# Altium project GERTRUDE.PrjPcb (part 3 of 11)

## Sheet MODULE_SAIL.SchDoc: MODULE SAIL
size A3; Author: Silvio Navaretti; CompanyName: ARDUINO; DrawnBy: Silvio Navaretti; Engineer: Silvio Navaretti; Organization: ARDUINO; SheetNumber: 4; SheetTotal: 51; RevAuthor: Silvio Navaretti
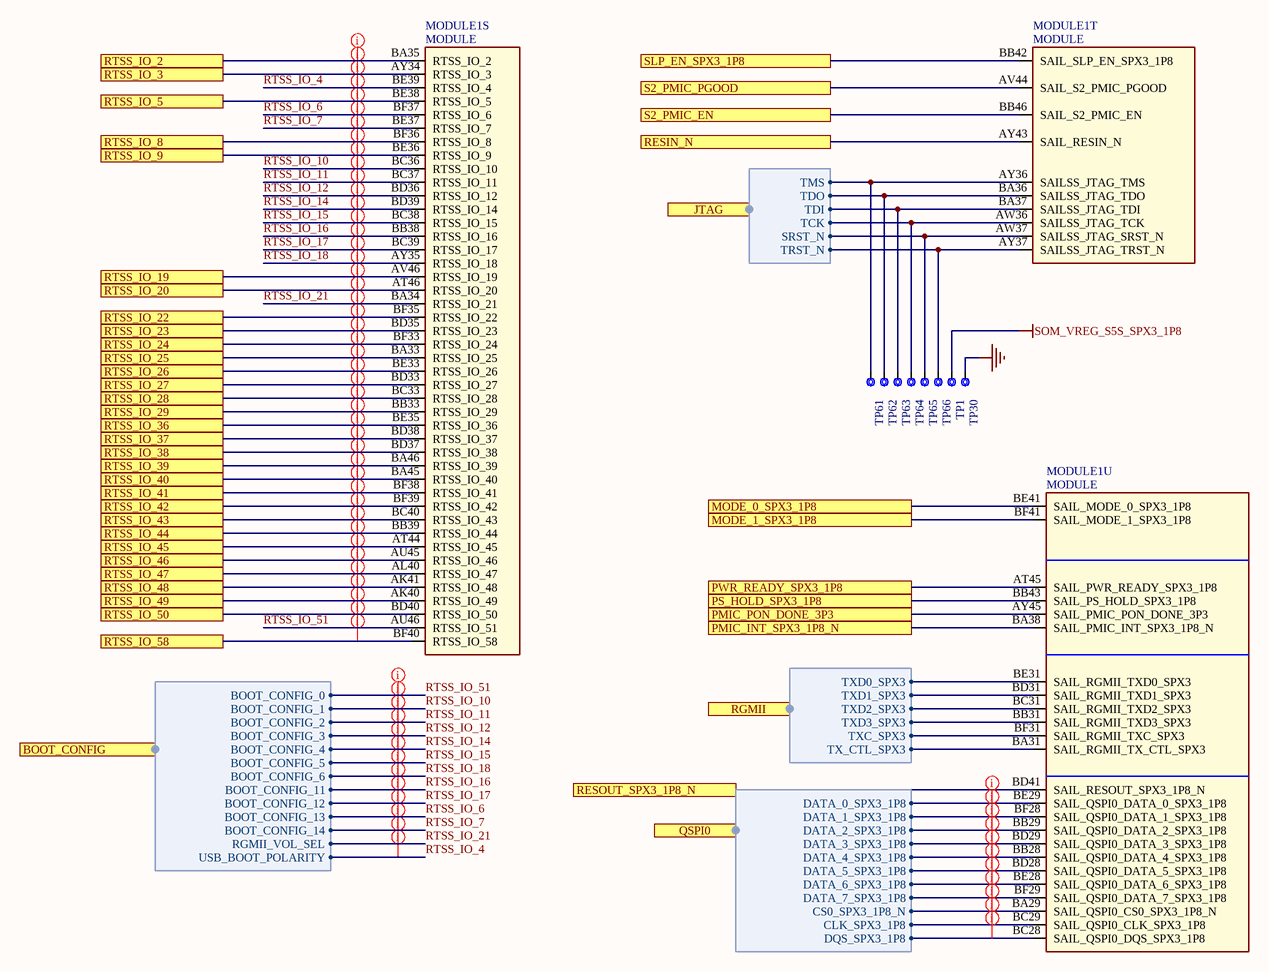
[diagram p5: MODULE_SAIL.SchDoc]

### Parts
MODULE1  MODULE  [MODULE]  (parts S,T,U of 22)
TP1  Test point 1.00mm  [TP-1.00MM]  (value not drawn)  (no BOM)
TP30  Test point 1.00mm  [TP-1.00MM]  (value not drawn)  (no BOM)
TP61  Test point 1.00mm  [TP-1.00MM]  (value not drawn)  (no BOM)
TP62  Test point 1.00mm  [TP-1.00MM]  (value not drawn)  (no BOM)
TP63  Test point 1.00mm  [TP-1.00MM]  (value not drawn)  (no BOM)
TP64  Test point 1.00mm  [TP-1.00MM]  (value not drawn)  (no BOM)
TP65  Test point 1.00mm  [TP-1.00MM]  (value not drawn)  (no BOM)
TP66  Test point 1.00mm  [TP-1.00MM]  (value not drawn)  (no BOM)

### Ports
BOOT_CONFIG (harness SOM_SAIL_BOOT_CONFIG), JTAG (harness SOM_SAIL_JTAG), MODE_0_SPX3_1P8, MODE_1_SPX3_1P8, PMIC_INT_SPX3_1P8_N, PMIC_PON_DONE_3P3, PS_HOLD_SPX3_1P8, PWR_READY_SPX3_1P8, QSPI0 (harness SOM_SAIL_QSPI0), RESIN_N, RESOUT_SPX3_1P8_N, RGMII (harness SOM_SAIL_RGMII), RTSS_IO_2, RTSS_IO_3, RTSS_IO_5, RTSS_IO_8, RTSS_IO_9, RTSS_IO_19, RTSS_IO_20, RTSS_IO_22, RTSS_IO_23, RTSS_IO_24, RTSS_IO_25, RTSS_IO_26, RTSS_IO_27, RTSS_IO_28, RTSS_IO_29, RTSS_IO_36, RTSS_IO_37, RTSS_IO_38, RTSS_IO_39, RTSS_IO_40, RTSS_IO_41, RTSS_IO_42, RTSS_IO_43, RTSS_IO_44, RTSS_IO_45, RTSS_IO_46, RTSS_IO_47, RTSS_IO_48, RTSS_IO_49, RTSS_IO_50, RTSS_IO_58, S2_PMIC_EN, S2_PMIC_PGOOD, SLP_EN_SPX3_1P8

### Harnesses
SOM_SAIL_JTAG: TMS, TDO, TDI, TCK, SRST_N, TRST_N
SOM_SAIL_RGMII: TXD0_SPX3, TXD1_SPX3, TXD2_SPX3, TXD3_SPX3, TXC_SPX3, TX_CTL_SPX3
SOM_SAIL_QSPI0: DATA_0_SPX3_1P8, DATA_1_SPX3_1P8, DATA_2_SPX3_1P8, DATA_3_SPX3_1P8, DATA_4_SPX3_1P8, DATA_5_SPX3_1P8, DATA_6_SPX3_1P8, DATA_7_SPX3_1P8, CS0_SPX3_1P8_N, CLK_SPX3_1P8, DQS_SPX3_1P8
SOM_SAIL_BOOT_CONFIG: BOOT_CONFIG_0, BOOT_CONFIG_1, BOOT_CONFIG_2, BOOT_CONFIG_3, BOOT_CONFIG_4, BOOT_CONFIG_5, BOOT_CONFIG_6, BOOT_CONFIG_11, BOOT_CONFIG_12, BOOT_CONFIG_13, BOOT_CONFIG_14, RGMII_VOL_SEL, USB_BOOT_POLARITY

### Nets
GND: TP30.X
SOM_VREG_S5S_SPX3_1P8: TP1.X
RTSS_IO_4: MODULE1.BE39(RTSS_IO_4) ; port BOOT_CONFIG.USB_BOOT_POLARITY
RTSS_IO_6: MODULE1.BF37(RTSS_IO_6) ; port BOOT_CONFIG.BOOT_CONFIG_13
RTSS_IO_7: MODULE1.BE37(RTSS_IO_7) ; port BOOT_CONFIG.BOOT_CONFIG_14
RTSS_IO_10: MODULE1.BC36(RTSS_IO_10) ; port BOOT_CONFIG.BOOT_CONFIG_1
RTSS_IO_11: MODULE1.BC37(RTSS_IO_11) ; port BOOT_CONFIG.BOOT_CONFIG_2
RTSS_IO_12: MODULE1.BD36(RTSS_IO_12) ; port BOOT_CONFIG.BOOT_CONFIG_3
RTSS_IO_14: MODULE1.BD39(RTSS_IO_14) ; port BOOT_CONFIG.BOOT_CONFIG_4
RTSS_IO_15: MODULE1.BC38(RTSS_IO_15) ; port BOOT_CONFIG.BOOT_CONFIG_5
RTSS_IO_16: MODULE1.BB38(RTSS_IO_16) ; port BOOT_CONFIG.BOOT_CONFIG_11
RTSS_IO_17: MODULE1.BC39(RTSS_IO_17) ; port BOOT_CONFIG.BOOT_CONFIG_12
RTSS_IO_18: MODULE1.AY35(RTSS_IO_18) ; port BOOT_CONFIG.BOOT_CONFIG_6
RTSS_IO_21: MODULE1.BA34(RTSS_IO_21) ; port BOOT_CONFIG.RGMII_VOL_SEL
RTSS_IO_51: MODULE1.AU46(RTSS_IO_51) ; port BOOT_CONFIG.BOOT_CONFIG_0
RTSS_IO_58_FORCE_USB_BOOT_SPX3_1P8: MODULE1.BF40(RTSS_IO_58) ; port RTSS_IO_58
RTSS_RESIN_N: MODULE1.AY43(SAIL_RESIN_N) ; port RESIN_N
SAIL_JTAG.SRST_N: MODULE1.AW37(SAILSS_JTAG_SRST_N) TP65.X ; port JTAG.SRST_N
SAIL_JTAG.TCK: MODULE1.AW36(SAILSS_JTAG_TCK) TP64.X ; port JTAG.TCK
SAIL_JTAG.TDI: MODULE1.BA37(SAILSS_JTAG_TDI) TP63.X ; port JTAG.TDI
SAIL_JTAG.TDO: MODULE1.BA36(SAILSS_JTAG_TDO) TP62.X ; port JTAG.TDO
SAIL_JTAG.TMS: MODULE1.AY36(SAILSS_JTAG_TMS) TP61.X ; port JTAG.TMS
SAIL_JTAG.TRST_N: MODULE1.AY37(SAILSS_JTAG_TRST_N) TP66.X ; port JTAG.TRST_N
NetMODULE1_AK40: MODULE1.AK40(RTSS_IO_49) ; port RTSS_IO_49
NetMODULE1_AK41: MODULE1.AK41(RTSS_IO_48) ; port RTSS_IO_48
NetMODULE1_AL40: MODULE1.AL40(RTSS_IO_47) ; port RTSS_IO_47
NetMODULE1_AT44: MODULE1.AT44(RTSS_IO_45) ; port RTSS_IO_45
NetMODULE1_AT45: MODULE1.AT45(SAIL_PWR_READY_SPX3_1P8) ; port PWR_READY_SPX3_1P8
NetMODULE1_AT46: MODULE1.AT46(RTSS_IO_20) ; port RTSS_IO_20
NetMODULE1_AU45: MODULE1.AU45(RTSS_IO_46) ; port RTSS_IO_46
NetMODULE1_AV44: MODULE1.AV44(SAIL_S2_PMIC_PGOOD) ; port S2_PMIC_PGOOD
NetMODULE1_AV46: MODULE1.AV46(RTSS_IO_19) ; port RTSS_IO_19
NetMODULE1_AY34: MODULE1.AY34(RTSS_IO_3) ; port RTSS_IO_3
NetMODULE1_AY45: MODULE1.AY45(SAIL_PMIC_PON_DONE_3P3) ; port PMIC_PON_DONE_3P3
NetMODULE1_BA29: MODULE1.BA29(SAIL_QSPI0_CS0_SPX3_1P8_N) ; port QSPI0.CS0_SPX3_1P8_N
NetMODULE1_BA31: MODULE1.BA31(SAIL_RGMII_TX_CTL_SPX3) ; port RGMII.TX_CTL_SPX3
NetMODULE1_BA33: MODULE1.BA33(RTSS_IO_25) ; port RTSS_IO_25
NetMODULE1_BA35: MODULE1.BA35(RTSS_IO_2) ; port RTSS_IO_2
NetMODULE1_BA38: MODULE1.BA38(SAIL_PMIC_INT_SPX3_1P8_N) ; port PMIC_INT_SPX3_1P8_N
NetMODULE1_BA45: MODULE1.BA45(RTSS_IO_40) ; port RTSS_IO_40
NetMODULE1_BA46: MODULE1.BA46(RTSS_IO_39) ; port RTSS_IO_39
NetMODULE1_BB28: MODULE1.BB28(SAIL_QSPI0_DATA_4_SPX3_1P8) ; port QSPI0.DATA_4_SPX3_1P8
NetMODULE1_BB29: MODULE1.BB29(SAIL_QSPI0_DATA_2_SPX3_1P8) ; port QSPI0.DATA_2_SPX3_1P8
NetMODULE1_BB31: MODULE1.BB31(SAIL_RGMII_TXD3_SPX3) ; port RGMII.TXD3_SPX3
NetMODULE1_BB33: MODULE1.BB33(RTSS_IO_29) ; port RTSS_IO_29
NetMODULE1_BB39: MODULE1.BB39(RTSS_IO_44) ; port RTSS_IO_44
NetMODULE1_BB42: MODULE1.BB42(SAIL_SLP_EN_SPX3_1P8) ; port SLP_EN_SPX3_1P8
NetMODULE1_BB43: MODULE1.BB43(SAIL_PS_HOLD_SPX3_1P8) ; port PS_HOLD_SPX3_1P8
NetMODULE1_BB46: MODULE1.BB46(SAIL_S2_PMIC_EN) ; port S2_PMIC_EN
NetMODULE1_BC28: MODULE1.BC28(SAIL_QSPI0_DQS_SPX3_1P8) ; port QSPI0.DQS_SPX3_1P8
NetMODULE1_BC29: MODULE1.BC29(SAIL_QSPI0_CLK_SPX3_1P8) ; port QSPI0.CLK_SPX3_1P8
NetMODULE1_BC31: MODULE1.BC31(SAIL_RGMII_TXD2_SPX3) ; port RGMII.TXD2_SPX3
NetMODULE1_BC33: MODULE1.BC33(RTSS_IO_28) ; port RTSS_IO_28
NetMODULE1_BC40: MODULE1.BC40(RTSS_IO_43) ; port RTSS_IO_43
NetMODULE1_BD28: MODULE1.BD28(SAIL_QSPI0_DATA_5_SPX3_1P8) ; port QSPI0.DATA_5_SPX3_1P8
NetMODULE1_BD29: MODULE1.BD29(SAIL_QSPI0_DATA_3_SPX3_1P8) ; port QSPI0.DATA_3_SPX3_1P8
NetMODULE1_BD31: MODULE1.BD31(SAIL_RGMII_TXD1_SPX3) ; port RGMII.TXD1_SPX3
NetMODULE1_BD33: MODULE1.BD33(RTSS_IO_27) ; port RTSS_IO_27
NetMODULE1_BD35: MODULE1.BD35(RTSS_IO_23) ; port RTSS_IO_23
NetMODULE1_BD37: MODULE1.BD37(RTSS_IO_38) ; port RTSS_IO_38
NetMODULE1_BD38: MODULE1.BD38(RTSS_IO_37) ; port RTSS_IO_37
NetMODULE1_BD40: MODULE1.BD40(RTSS_IO_50) ; port RTSS_IO_50
NetMODULE1_BD41: MODULE1.BD41(SAIL_RESOUT_SPX3_1P8_N) ; port RESOUT_SPX3_1P8_N
NetMODULE1_BE28: MODULE1.BE28(SAIL_QSPI0_DATA_6_SPX3_1P8) ; port QSPI0.DATA_6_SPX3_1P8
NetMODULE1_BE29: MODULE1.BE29(SAIL_QSPI0_DATA_0_SPX3_1P8) ; port QSPI0.DATA_0_SPX3_1P8
NetMODULE1_BE31: MODULE1.BE31(SAIL_RGMII_TXD0_SPX3) ; port RGMII.TXD0_SPX3
NetMODULE1_BE33: MODULE1.BE33(RTSS_IO_26) ; port RTSS_IO_26
NetMODULE1_BE35: MODULE1.BE35(RTSS_IO_36) ; port RTSS_IO_36
NetMODULE1_BE36: MODULE1.BE36(RTSS_IO_9) ; port RTSS_IO_9
NetMODULE1_BE38: MODULE1.BE38(RTSS_IO_5) ; port RTSS_IO_5
NetMODULE1_BE41: MODULE1.BE41(SAIL_MODE_0_SPX3_1P8) ; port MODE_0_SPX3_1P8
NetMODULE1_BF28: MODULE1.BF28(SAIL_QSPI0_DATA_1_SPX3_1P8) ; port QSPI0.DATA_1_SPX3_1P8
NetMODULE1_BF29: MODULE1.BF29(SAIL_QSPI0_DATA_7_SPX3_1P8) ; port QSPI0.DATA_7_SPX3_1P8
NetMODULE1_BF31: MODULE1.BF31(SAIL_RGMII_TXC_SPX3) ; port RGMII.TXC_SPX3
NetMODULE1_BF33: MODULE1.BF33(RTSS_IO_24) ; port RTSS_IO_24
NetMODULE1_BF35: MODULE1.BF35(RTSS_IO_22) ; port RTSS_IO_22
NetMODULE1_BF36: MODULE1.BF36(RTSS_IO_8) ; port RTSS_IO_8
NetMODULE1_BF38: MODULE1.BF38(RTSS_IO_41) ; port RTSS_IO_41
NetMODULE1_BF39: MODULE1.BF39(RTSS_IO_42) ; port RTSS_IO_42
NetMODULE1_BF41: MODULE1.BF41(SAIL_MODE_1_SPX3_1P8) ; port MODE_1_SPX3_1P8

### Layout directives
net class NET_SOM_SAIL_BOOT: RTSS_IO_4, RTSS_IO_6, RTSS_IO_7, RTSS_IO_10, RTSS_IO_11, RTSS_IO_12, RTSS_IO_14, RTSS_IO_15, RTSS_IO_16, RTSS_IO_17, RTSS_IO_18, RTSS_IO_21, RTSS_IO_51
net class NET_SOM_SAIL_IO: NetMODULE1_AK40, NetMODULE1_AK41, NetMODULE1_AL40, NetMODULE1_AT44, NetMODULE1_AT46, NetMODULE1_AU45, NetMODULE1_AV46, NetMODULE1_AY34, NetMODULE1_BA33, NetMODULE1_BA35, NetMODULE1_BA45, NetMODULE1_BA46, NetMODULE1_BB33, NetMODULE1_BB39, NetMODULE1_BC33, NetMODULE1_BC40, NetMODULE1_BD33, NetMODULE1_BD35, NetMODULE1_BD37, NetMODULE1_BD38, NetMODULE1_BD40, NetMODULE1_BE33, NetMODULE1_BE35, NetMODULE1_BE36, NetMODULE1_BE38, NetMODULE1_BF33, NetMODULE1_BF35, NetMODULE1_BF36, NetMODULE1_BF38, NetMODULE1_BF39, RTSS_IO_4, RTSS_IO_6, RTSS_IO_7, RTSS_IO_10, RTSS_IO_11, RTSS_IO_12, RTSS_IO_14, RTSS_IO_15, RTSS_IO_16, RTSS_IO_17, RTSS_IO_18, RTSS_IO_21, RTSS_IO_51, RTSS_IO_58_FORCE_USB_BOOT_SPX3_1P8
net class NET_SOM_SAIL_QSPI0: NetMODULE1_BA29, NetMODULE1_BB28, NetMODULE1_BB29, NetMODULE1_BC28, NetMODULE1_BC29, NetMODULE1_BD28, NetMODULE1_BD29, NetMODULE1_BE28, NetMODULE1_BE29, NetMODULE1_BF28, NetMODULE1_BF29

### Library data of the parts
MODULE1 = M0029-A.19: MODULE BGA 1883 balls 57.5x57.5mm; Manufacturer: Qualcomm; Code Arduino: M0029
TP1 TP30 TP61-TP66 = UT0013-A.6: Part Number: This is not a component

## Sheet MODULE_MD.SchDoc: MODULE MAIN DOMAIN
size A3; Author: Silvio Navaretti; CompanyName: ARDUINO; DrawnBy: Silvio Navaretti; Engineer: Silvio Navaretti; Organization: ARDUINO; SheetNumber: 3; SheetTotal: 51; RevAuthor: Silvio Navaretti
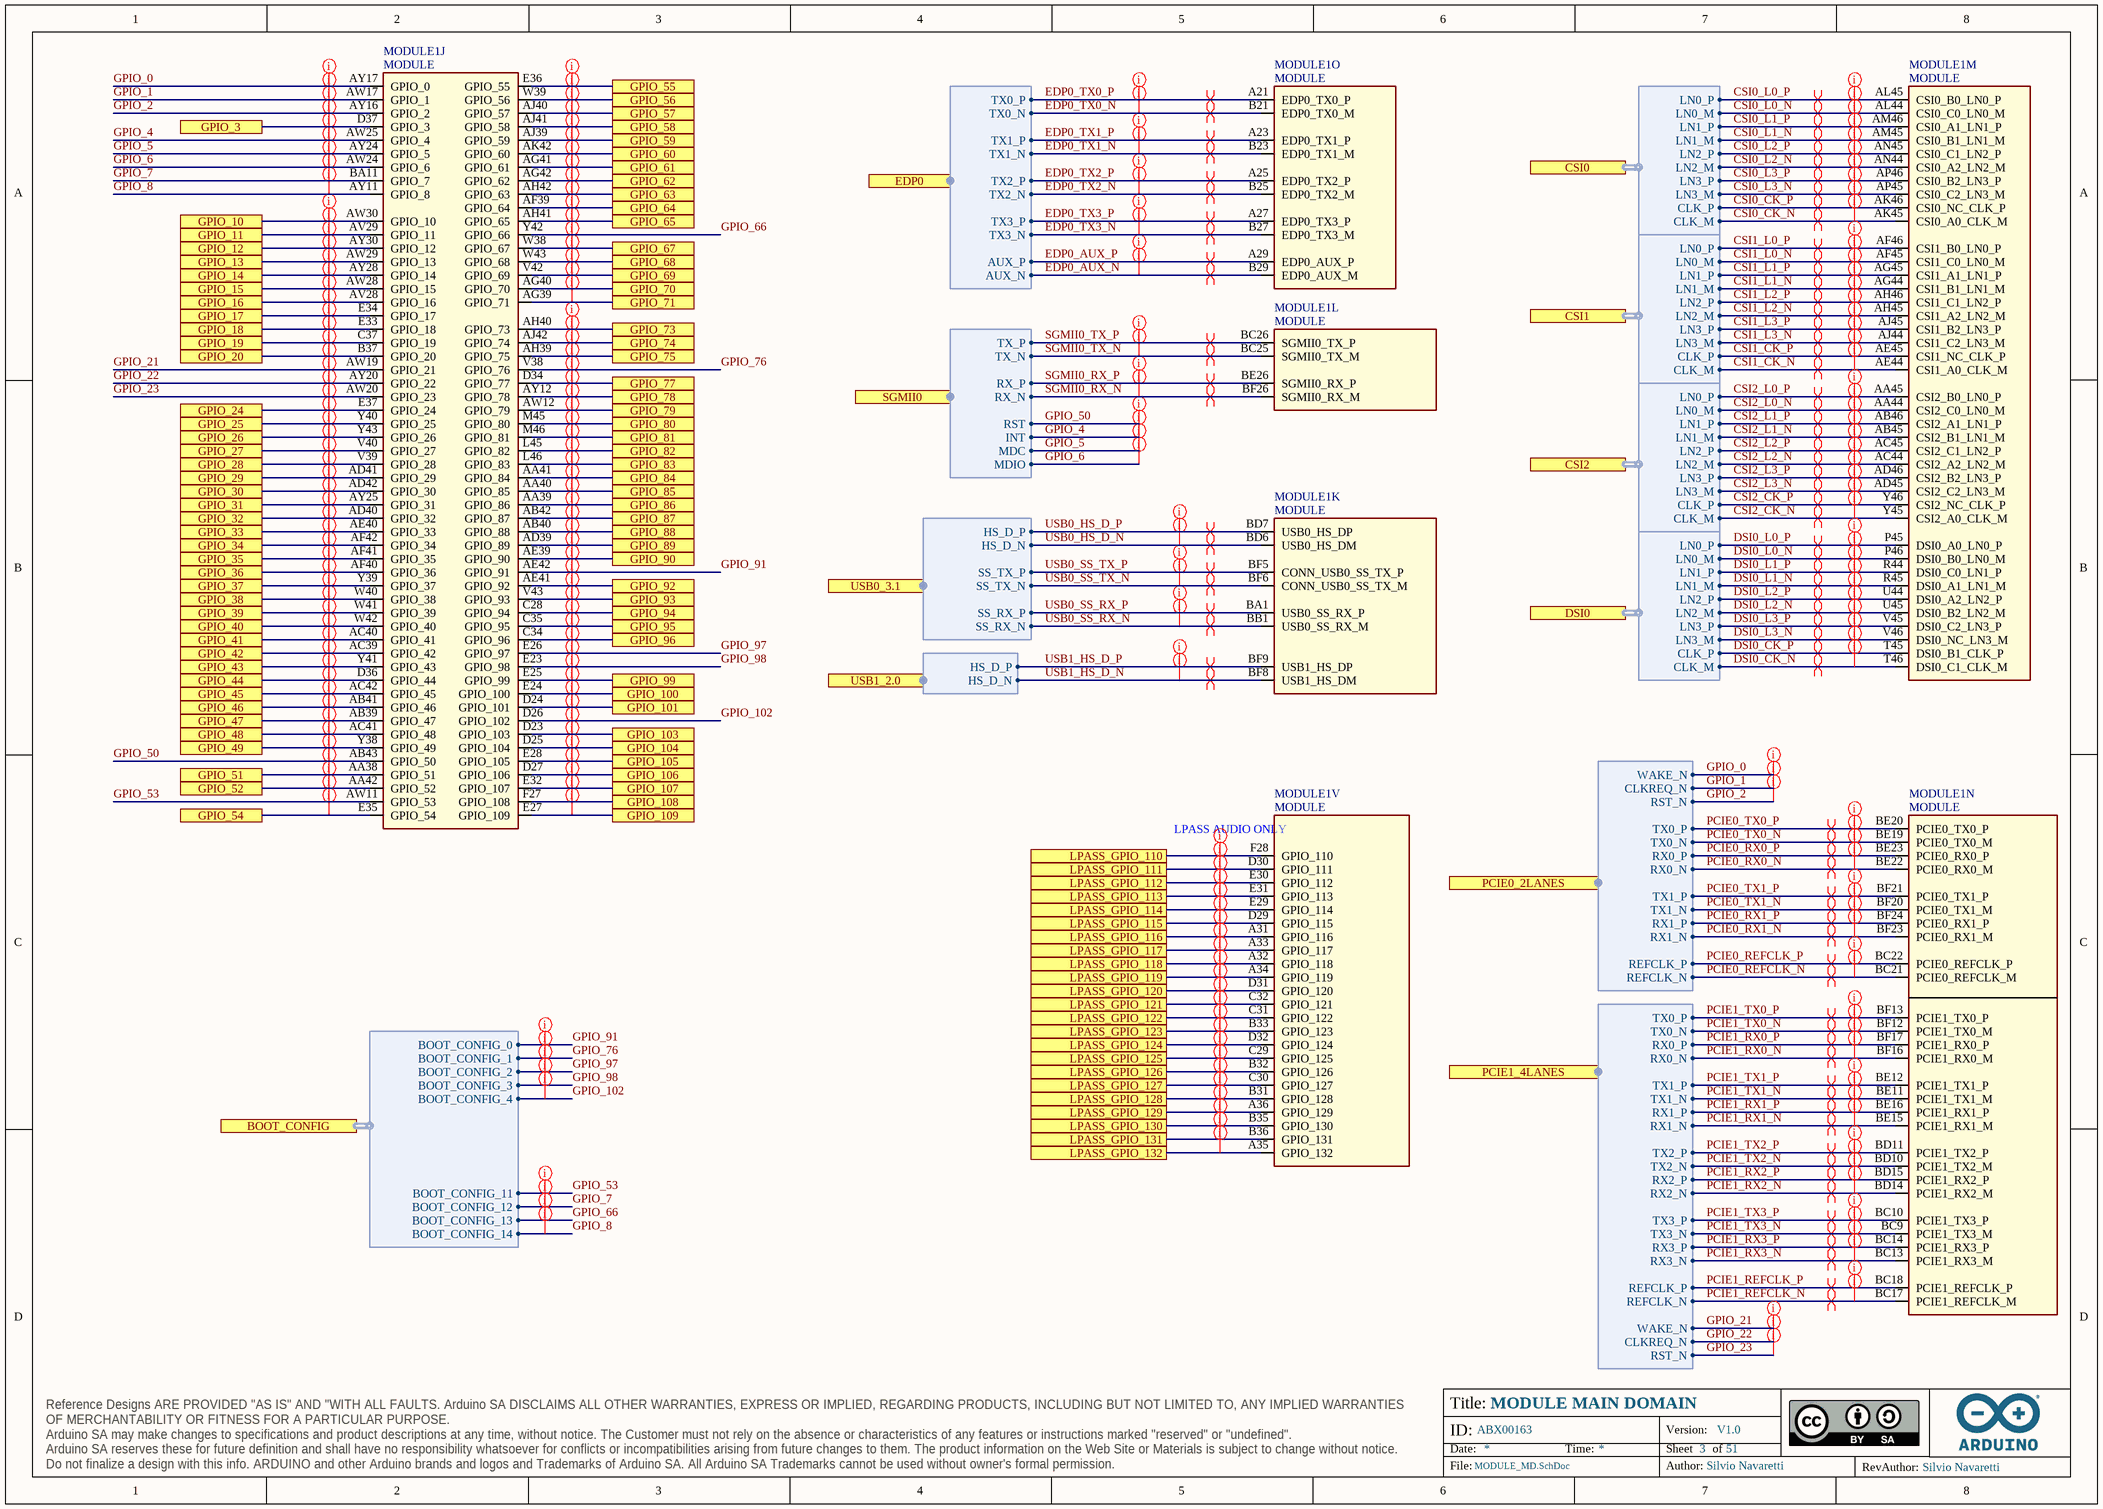
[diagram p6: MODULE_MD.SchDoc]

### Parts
MODULE1  MODULE  [MODULE]  (parts J,K,L,M,N,O,V of 22)

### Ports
BOOT_CONFIG (harness SOM_MD_BOOT_CONFIG), CSI0 (harness MIPI_4LANES), CSI1 (harness MIPI_4LANES), CSI2 (harness MIPI_4LANES), DSI0 (harness MIPI_4LANES), EDP0 (harness SOM_MD_EDP0), GPIO_3, GPIO_10, GPIO_11, GPIO_12, GPIO_13, GPIO_14, GPIO_15, GPIO_16, GPIO_17, GPIO_18, GPIO_19, GPIO_20, GPIO_24, GPIO_25, GPIO_26, GPIO_27, GPIO_28, GPIO_29, GPIO_30, GPIO_31, GPIO_32, GPIO_33, GPIO_34, GPIO_35, GPIO_36, GPIO_37, GPIO_38, GPIO_39, GPIO_40, GPIO_41, GPIO_42, GPIO_43, GPIO_44, GPIO_45, GPIO_46, GPIO_47, GPIO_48, GPIO_49, GPIO_51, GPIO_52, GPIO_54, GPIO_55, GPIO_56, GPIO_57, GPIO_58, GPIO_59, GPIO_60, GPIO_61, GPIO_62, GPIO_63, GPIO_64, GPIO_65, GPIO_67, GPIO_68, GPIO_69, GPIO_70, GPIO_71, GPIO_73, GPIO_74, GPIO_75, GPIO_77, GPIO_78, GPIO_79, GPIO_80, GPIO_81, GPIO_82, GPIO_83, GPIO_84, GPIO_85, GPIO_86, GPIO_87, GPIO_88, GPIO_89, GPIO_90, GPIO_92, GPIO_93, GPIO_94, GPIO_95, GPIO_96, GPIO_99, GPIO_100, GPIO_101, GPIO_103, GPIO_104, GPIO_105, GPIO_106, GPIO_107, GPIO_108, GPIO_109, LPASS_GPIO_110, LPASS_GPIO_111, LPASS_GPIO_112, LPASS_GPIO_113, LPASS_GPIO_114, LPASS_GPIO_115, LPASS_GPIO_116, LPASS_GPIO_117, LPASS_GPIO_118, LPASS_GPIO_119, LPASS_GPIO_120, LPASS_GPIO_121, LPASS_GPIO_122, LPASS_GPIO_123, LPASS_GPIO_124, LPASS_GPIO_125, LPASS_GPIO_126, LPASS_GPIO_127, LPASS_GPIO_128, LPASS_GPIO_129, LPASS_GPIO_130, LPASS_GPIO_131, LPASS_GPIO_132, PCIE0_2LANES (harness SOM_MD_PCIE0), PCIE1_4LANES (harness SOM_MD_PCIE1), SGMII0 (harness SOM_MD_SGMII0), USB0_3.1 (harness SOM_MD_USB0), USB1_2.0 (harness SOM_MD_USB1)

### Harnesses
MIPI_4LANES: LN3_M, LN2_M, LN2_P, LN0_M, LN0_P, CLK_M, CLK_P, LN1_M, LN1_P, LN3_P
SOM_MD_SGMII0: RX_P, RX_N, TX_P, TX_N, RST, MDC, INT, MDIO
SOM_MD_EDP0: TX0_P, TX1_P, TX2_P, TX3_P, AUX_P, TX0_N, TX1_N, TX2_N, TX3_N, AUX_N
SOM_MD_USB0: SS_TX_N, SS_TX_P, HS_D_P, HS_D_N, SS_RX_P, SS_RX_N
SOM_MD_USB1: HS_D_P, HS_D_N
SOM_MD_PCIE0: RX0_N, RX0_P, TX0_P, TX0_N, RX1_N, RX1_P, TX1_P, TX1_N, REFCLK_N, REFCLK_P, WAKE_N, CLKREQ_N, RST_N
SOM_MD_PCIE1: RX0_N, RX0_P, TX0_P, TX0_N, RX1_N, RX1_P, TX1_P, TX1_N, REFCLK_N, REFCLK_P, RX2_N, RX2_P, TX2_P, TX2_N, RX3_N, RX3_P, TX3_P, TX3_N, WAKE_N, CLKREQ_N, RST_N
SOM_MD_BOOT_CONFIG: BOOT_CONFIG_0, BOOT_CONFIG_1, BOOT_CONFIG_2, BOOT_CONFIG_3, BOOT_CONFIG_4, BOOT_CONFIG_11, BOOT_CONFIG_12, BOOT_CONFIG_13, BOOT_CONFIG_14

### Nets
CSI0_CK_N: MODULE1.AK45(CSI0_A0_CLK_M) ; port CSI0.CLK_M
CSI0_CK_P: MODULE1.AK46(CSI0_NC_CLK_P) ; port CSI0.CLK_P
CSI0_L0_N: MODULE1.AL44(CSI0_C0_LN0_M) ; port CSI0.LN0_M
CSI0_L0_P: MODULE1.AL45(CSI0_B0_LN0_P) ; port CSI0.LN0_P
CSI0_L1_N: MODULE1.AM45(CSI0_B1_LN1_M) ; port CSI0.LN1_M
CSI0_L1_P: MODULE1.AM46(CSI0_A1_LN1_P) ; port CSI0.LN1_P
CSI0_L2_N: MODULE1.AN44(CSI0_A2_LN2_M) ; port CSI0.LN2_M
CSI0_L2_P: MODULE1.AN45(CSI0_C1_LN2_P) ; port CSI0.LN2_P
CSI0_L3_N: MODULE1.AP45(CSI0_C2_LN3_M) ; port CSI0.LN3_M
CSI0_L3_P: MODULE1.AP46(CSI0_B2_LN3_P) ; port CSI0.LN3_P
CSI1_CK_N: MODULE1.AE44(CSI1_A0_CLK_M) ; port CSI1.CLK_M
CSI1_CK_P: MODULE1.AE45(CSI1_NC_CLK_P) ; port CSI1.CLK_P
CSI1_L0_N: MODULE1.AF45(CSI1_C0_LN0_M) ; port CSI1.LN0_M
CSI1_L0_P: MODULE1.AF46(CSI1_B0_LN0_P) ; port CSI1.LN0_P
CSI1_L1_N: MODULE1.AG44(CSI1_B1_LN1_M) ; port CSI1.LN1_M
CSI1_L1_P: MODULE1.AG45(CSI1_A1_LN1_P) ; port CSI1.LN1_P
CSI1_L2_N: MODULE1.AH45(CSI1_A2_LN2_M) ; port CSI1.LN2_M
CSI1_L2_P: MODULE1.AH46(CSI1_C1_LN2_P) ; port CSI1.LN2_P
CSI1_L3_N: MODULE1.AJ44(CSI1_C2_LN3_M) ; port CSI1.LN3_M
CSI1_L3_P: MODULE1.AJ45(CSI1_B2_LN3_P) ; port CSI1.LN3_P
CSI2_CK_N: MODULE1.Y45(CSI2_A0_CLK_M) ; port CSI2.CLK_M
CSI2_CK_P: MODULE1.Y46(CSI2_NC_CLK_P) ; port CSI2.CLK_P
CSI2_L0_N: MODULE1.AA44(CSI2_C0_LN0_M) ; port CSI2.LN0_M
CSI2_L0_P: MODULE1.AA45(CSI2_B0_LN0_P) ; port CSI2.LN0_P
CSI2_L1_N: MODULE1.AB45(CSI2_B1_LN1_M) ; port CSI2.LN1_M
CSI2_L1_P: MODULE1.AB46(CSI2_A1_LN1_P) ; port CSI2.LN1_P
CSI2_L2_N: MODULE1.AC44(CSI2_A2_LN2_M) ; port CSI2.LN2_M
CSI2_L2_P: MODULE1.AC45(CSI2_C1_LN2_P) ; port CSI2.LN2_P
CSI2_L3_N: MODULE1.AD45(CSI2_C2_LN3_M) ; port CSI2.LN3_M
CSI2_L3_P: MODULE1.AD46(CSI2_B2_LN3_P) ; port CSI2.LN3_P
CTS_1V8: MODULE1.AA41(GPIO_84) ; port GPIO_84
DSI0_CK_N: MODULE1.T46(DSI0_C1_CLK_M) ; port DSI0.CLK_M
DSI0_CK_P: MODULE1.T45(DSI0_B1_CLK_P) ; port DSI0.CLK_P
DSI0_L0_N: MODULE1.P46(DSI0_B0_LN0_M) ; port DSI0.LN0_M
DSI0_L0_P: MODULE1.P45(DSI0_A0_LN0_P) ; port DSI0.LN0_P
DSI0_L1_N: MODULE1.R45(DSI0_A1_LN1_M) ; port DSI0.LN1_M
DSI0_L1_P: MODULE1.R44(DSI0_C0_LN1_P) ; port DSI0.LN1_P
DSI0_L2_N: MODULE1.U45(DSI0_B2_LN2_M) ; port DSI0.LN2_M
DSI0_L2_P: MODULE1.U44(DSI0_A2_LN2_P) ; port DSI0.LN2_P
DSI0_L3_N: MODULE1.V46(DSI0_NC_LN3_M) ; port DSI0.LN3_M
DSI0_L3_P: MODULE1.V45(DSI0_C2_LN3_P) ; port DSI0.LN3_P
EDP0_AUX_N: MODULE1.B29(EDP0_AUX_M) ; port EDP0.AUX_N
EDP0_AUX_P: MODULE1.A29(EDP0_AUX_P) ; port EDP0.AUX_P
EDP0_TX0_N: MODULE1.B21(EDP0_TX0_M) ; port EDP0.TX0_N
EDP0_TX0_P: MODULE1.A21(EDP0_TX0_P) ; port EDP0.TX0_P
EDP0_TX1_N: MODULE1.B23(EDP0_TX1_M) ; port EDP0.TX1_N
EDP0_TX1_P: MODULE1.A23(EDP0_TX1_P) ; port EDP0.TX1_P
EDP0_TX2_N: MODULE1.B25(EDP0_TX2_M) ; port EDP0.TX2_N
EDP0_TX2_P: MODULE1.A25(EDP0_TX2_P) ; port EDP0.TX2_P
EDP0_TX3_N: MODULE1.B27(EDP0_TX3_M) ; port EDP0.TX3_N
EDP0_TX3_P: MODULE1.A27(EDP0_TX3_P) ; port EDP0.TX3_P
GPIO_0: MODULE1.AY17(GPIO_0) ; port PCIE0_2LANES.WAKE_N
GPIO_1: MODULE1.AW17(GPIO_1) ; port PCIE0_2LANES.CLKREQ_N  [project net CLKREQ_N_1V8]
GPIO_2: MODULE1.AY16(GPIO_2) ; port PCIE0_2LANES.RST_N
GPIO_4: MODULE1.AW25(GPIO_4) ; port SGMII0.INT
GPIO_5: MODULE1.AY24(GPIO_5) ; port SGMII0.MDC
GPIO_6: MODULE1.AW24(GPIO_6) ; port SGMII0.MDIO
GPIO_7: MODULE1.BA11(GPIO_7) ; port BOOT_CONFIG.BOOT_CONFIG_12
GPIO_8: MODULE1.AY11(GPIO_8) ; port BOOT_CONFIG.BOOT_CONFIG_14
GPIO_21: MODULE1.AW19(GPIO_21) ; port PCIE1_4LANES.WAKE_N
GPIO_22: MODULE1.AY20(GPIO_22) ; port PCIE1_4LANES.CLKREQ_N
GPIO_23: MODULE1.AW20(GPIO_23) ; port PCIE1_4LANES.RST_N
GPIO_50: MODULE1.AB43(GPIO_50) ; port SGMII0.RST
GPIO_53: MODULE1.AW11(GPIO_53) ; port BOOT_CONFIG.BOOT_CONFIG_11
GPIO_66: MODULE1.Y42(GPIO_66) ; port BOOT_CONFIG.BOOT_CONFIG_13
GPIO_76: MODULE1.V38(GPIO_76) ; port BOOT_CONFIG.BOOT_CONFIG_1
GPIO_91: MODULE1.AE42(GPIO_91) ; port BOOT_CONFIG.BOOT_CONFIG_0
GPIO_97: MODULE1.E26(GPIO_97) ; port BOOT_CONFIG.BOOT_CONFIG_2
GPIO_98: MODULE1.E23(GPIO_98) ; port BOOT_CONFIG.BOOT_CONFIG_3
GPIO_102: MODULE1.D26(GPIO_102) ; port BOOT_CONFIG.BOOT_CONFIG_4
I2S_DATA0: MODULE1.A32(GPIO_118) ; port LPASS_GPIO_118
I2S_DATA1: MODULE1.A34(GPIO_119) ; port LPASS_GPIO_119
I2S_SCK: MODULE1.A31(GPIO_116) ; port LPASS_GPIO_116
I2S_WS: MODULE1.A33(GPIO_117) ; port LPASS_GPIO_117
MD_CCI_I2C0.SCL: MODULE1.AJ41(GPIO_58) ; port GPIO_58
MD_CCI_I2C0.SDA: MODULE1.AJ40(GPIO_57) ; port GPIO_57
MD_CCI_I2C2.SCL: MODULE1.AK42(GPIO_60) ; port GPIO_60
MD_CCI_I2C2.SDA: MODULE1.AJ39(GPIO_59) ; port GPIO_59
MD_CCI_I2C3.SCL: MODULE1.AD40(GPIO_32) ; port GPIO_32
MD_CCI_I2C3.SDA: MODULE1.AY25(GPIO_31) ; port GPIO_31
MD_CCI_I2C4.SCL: MODULE1.AG42(GPIO_62) ; port GPIO_62
MD_CCI_I2C4.SDA: MODULE1.AG41(GPIO_61) ; port GPIO_61
MD_GPIO_3: MODULE1.D37(GPIO_3) ; port GPIO_3
MD_GPIO_10: MODULE1.AW30(GPIO_10) ; port GPIO_10
MD_GPIO_11: MODULE1.AV29(GPIO_11) ; port GPIO_11
MD_GPIO_12: MODULE1.AY30(GPIO_12) ; port GPIO_12
MD_GPIO_13: MODULE1.AW29(GPIO_13) ; port GPIO_13
MD_GPIO_14: MODULE1.AY28(GPIO_14) ; port GPIO_14
MD_GPIO_15: MODULE1.AW28(GPIO_15) ; port GPIO_15
MD_GPIO_16: MODULE1.AV28(GPIO_16) ; port GPIO_16
MD_GPIO_17: MODULE1.E34(GPIO_17) ; port GPIO_17
MD_GPIO_18: MODULE1.E33(GPIO_18) ; port GPIO_18
MD_GPIO_19: MODULE1.C37(GPIO_19) ; port GPIO_19
MD_GPIO_20: MODULE1.B37(GPIO_20) ; port GPIO_20
MD_GPIO_24: MODULE1.E37(GPIO_24) ; port GPIO_24
MD_GPIO_25: MODULE1.Y40(GPIO_25) ; port GPIO_25
MD_GPIO_26: MODULE1.Y43(GPIO_26) ; port GPIO_26
MD_GPIO_27: MODULE1.V40(GPIO_27) ; port GPIO_27
MD_GPIO_28: MODULE1.V39(GPIO_28) ; port GPIO_28
MD_GPIO_29: MODULE1.AD41(GPIO_29) ; port GPIO_29
MD_GPIO_30: MODULE1.AD42(GPIO_30) ; port GPIO_30
MD_GPIO_33: MODULE1.AE40(GPIO_33) ; port GPIO_33
MD_GPIO_34: MODULE1.AF42(GPIO_34) ; port GPIO_34
MD_GPIO_35: MODULE1.AF41(GPIO_35) ; port GPIO_35
MD_GPIO_36: MODULE1.AF40(GPIO_36) ; port GPIO_36
MD_GPIO_37: MODULE1.Y39(GPIO_37) ; port GPIO_37
MD_GPIO_38: MODULE1.W40(GPIO_38) ; port GPIO_38
MD_GPIO_39: MODULE1.W41(GPIO_39) ; port GPIO_39
MD_GPIO_40: MODULE1.W42(GPIO_40) ; port GPIO_40
MD_GPIO_41: MODULE1.AC40(GPIO_41) ; port GPIO_41
MD_GPIO_42: MODULE1.AC39(GPIO_42) ; port GPIO_42
MD_GPIO_43: MODULE1.Y41(GPIO_43) ; port GPIO_43
MD_GPIO_44: MODULE1.D36(GPIO_44) ; port GPIO_44
MD_GPIO_45: MODULE1.AC42(GPIO_45) ; port GPIO_45
MD_GPIO_46: MODULE1.AB41(GPIO_46) ; port GPIO_46
MD_GPIO_47: MODULE1.AB39(GPIO_47) ; port GPIO_47
MD_GPIO_48: MODULE1.AC41(GPIO_48) ; port GPIO_48
MD_GPIO_49: MODULE1.Y38(GPIO_49) ; port GPIO_49
MD_GPIO_51: MODULE1.AA38(GPIO_51) ; port GPIO_51
MD_GPIO_52: MODULE1.AA42(GPIO_52) ; port GPIO_52
MD_GPIO_54: MODULE1.E35(GPIO_54) ; port GPIO_54
MD_GPIO_55: MODULE1.E36(GPIO_55) ; port GPIO_55
MD_GPIO_56: MODULE1.W39(GPIO_56) ; port GPIO_56
MD_GPIO_63: MODULE1.AH42(GPIO_63) ; port GPIO_63
MD_GPIO_64: MODULE1.AF39(GPIO_64) ; port GPIO_64
MD_GPIO_65: MODULE1.AH41(GPIO_65) ; port GPIO_65
MD_GPIO_67: MODULE1.W38(GPIO_67) ; port GPIO_67
MD_GPIO_68: MODULE1.W43(GPIO_68) ; port GPIO_68
MD_GPIO_69: MODULE1.V42(GPIO_69) ; port GPIO_69
MD_GPIO_70: MODULE1.AG40(GPIO_70) ; port GPIO_70
MD_GPIO_71: MODULE1.AG39(GPIO_71) ; port GPIO_71
MD_GPIO_73: MODULE1.AH40(GPIO_73) ; port GPIO_73
MD_GPIO_74: MODULE1.AJ42(GPIO_74) ; port GPIO_74
MD_GPIO_75: MODULE1.AH39(GPIO_75) ; port GPIO_75
MD_GPIO_77: MODULE1.D34(GPIO_77) ; port GPIO_77
MD_GPIO_78: MODULE1.AY12(GPIO_78) ; port GPIO_78
MD_GPIO_79: MODULE1.AW12(GPIO_79) ; port GPIO_79
MD_GPIO_80: MODULE1.M45(GPIO_80) ; port GPIO_80
MD_GPIO_81: MODULE1.M46(GPIO_81) ; port GPIO_81
MD_GPIO_82: MODULE1.L45(GPIO_82) ; port GPIO_82
MD_GPIO_83: MODULE1.L46(GPIO_83) ; port GPIO_83
MD_GPIO_85: MODULE1.AA40(GPIO_85) ; port GPIO_85
MD_GPIO_86: MODULE1.AA39(GPIO_86) ; port GPIO_86
MD_GPIO_87: MODULE1.AB42(GPIO_87) ; port GPIO_87
MD_GPIO_88: MODULE1.AB40(GPIO_88) ; port GPIO_88
MD_GPIO_89: MODULE1.AD39(GPIO_89) ; port GPIO_89
MD_GPIO_90: MODULE1.AE39(GPIO_90) ; port GPIO_90
MD_GPIO_92: MODULE1.AE41(GPIO_92) ; port GPIO_92
MD_GPIO_93: MODULE1.V43(GPIO_93) ; port GPIO_93
MD_GPIO_94: MODULE1.C28(GPIO_94) ; port GPIO_94
MD_GPIO_95: MODULE1.C35(GPIO_95) ; port GPIO_95
MD_GPIO_96: MODULE1.C34(GPIO_96) ; port GPIO_96
MD_GPIO_99: MODULE1.E25(GPIO_99) ; port GPIO_99
MD_GPIO_100: MODULE1.E24(GPIO_100) ; port GPIO_100
MD_GPIO_101: MODULE1.D24(GPIO_101) ; port GPIO_101
MD_GPIO_103: MODULE1.D23(GPIO_103) ; port GPIO_103
MD_GPIO_104: MODULE1.D25(GPIO_104) ; port GPIO_104
MD_GPIO_105: MODULE1.E28(GPIO_105) ; port GPIO_105
MD_GPIO_106: MODULE1.D27(GPIO_106) ; port GPIO_106
MD_GPIO_107: MODULE1.E32(GPIO_107) ; port GPIO_107
MD_GPIO_108: MODULE1.F27(GPIO_108) ; port GPIO_108
MD_GPIO_109: MODULE1.E27(GPIO_109) ; port GPIO_109
MD_LPASS_GPIO_110: MODULE1.F28(GPIO_110) ; port LPASS_GPIO_110
MD_LPASS_GPIO_111: MODULE1.D30(GPIO_111) ; port LPASS_GPIO_111
MD_LPASS_GPIO_112: MODULE1.E30(GPIO_112) ; port LPASS_GPIO_112
MD_LPASS_GPIO_113: MODULE1.E31(GPIO_113) ; port LPASS_GPIO_113
MD_LPASS_GPIO_115: MODULE1.D29(GPIO_115) ; port LPASS_GPIO_115
MD_LPASS_GPIO_120: MODULE1.D31(GPIO_120) ; port LPASS_GPIO_120
MD_LPASS_GPIO_121: MODULE1.C32(GPIO_121) ; port LPASS_GPIO_121
MD_LPASS_GPIO_122: MODULE1.C31(GPIO_122) ; port LPASS_GPIO_122
MD_LPASS_GPIO_123: MODULE1.B33(GPIO_123) ; port LPASS_GPIO_123
MD_LPASS_GPIO_125: MODULE1.C29(GPIO_125) ; port LPASS_GPIO_125
MD_LPASS_GPIO_126: MODULE1.B32(GPIO_126) ; port LPASS_GPIO_126
MD_LPASS_GPIO_127: MODULE1.C30(GPIO_127) ; port LPASS_GPIO_127
MD_LPASS_GPIO_129: MODULE1.A36(GPIO_129) ; port LPASS_GPIO_129
MD_LPASS_GPIO_130: MODULE1.B35(GPIO_130) ; port LPASS_GPIO_130
MD_LPASS_GPIO_131: MODULE1.B36(GPIO_131) ; port LPASS_GPIO_131
MD_LPASS_GPIO_132: MODULE1.A35(GPIO_132) ; port LPASS_GPIO_132
PCIE0_REFCLK_N: MODULE1.BC21(PCIE0_REFCLK_M) ; port PCIE0_2LANES.REFCLK_N  [project net MD_PCIE0_2LANES.REFCLK_N]
PCIE0_REFCLK_P: MODULE1.BC22(PCIE0_REFCLK_P) ; port PCIE0_2LANES.REFCLK_P  [project net MD_PCIE0_2LANES.REFCLK_P]
PCIE0_RX0_N: MODULE1.BE22(PCIE0_RX0_M) ; port PCIE0_2LANES.RX0_N  [project net MD_PCIE0_2LANES.RX0_N]
PCIE0_RX0_P: MODULE1.BE23(PCIE0_RX0_P) ; port PCIE0_2LANES.RX0_P  [project net MD_PCIE0_2LANES.RX0_P]
PCIE0_RX1_N: MODULE1.BF23(PCIE0_RX1_M) ; port PCIE0_2LANES.RX1_N  [project net MD_PCIE0_2LANES.RX1_N]
PCIE0_RX1_P: MODULE1.BF24(PCIE0_RX1_P) ; port PCIE0_2LANES.RX1_P  [project net MD_PCIE0_2LANES.RX1_P]
PCIE0_TX0_N: MODULE1.BE19(PCIE0_TX0_M) ; port PCIE0_2LANES.TX0_N  [project net MD_PCIE0_2LANES.TX0_N]
PCIE0_TX0_P: MODULE1.BE20(PCIE0_TX0_P) ; port PCIE0_2LANES.TX0_P  [project net MD_PCIE0_2LANES.TX0_P]
PCIE0_TX1_N: MODULE1.BF20(PCIE0_TX1_M) ; port PCIE0_2LANES.TX1_N  [project net MD_PCIE0_2LANES.TX1_N]
PCIE0_TX1_P: MODULE1.BF21(PCIE0_TX1_P) ; port PCIE0_2LANES.TX1_P  [project net MD_PCIE0_2LANES.TX1_P]
PCIE1_REFCLK_N: MODULE1.BC17(PCIE1_REFCLK_M) ; port PCIE1_4LANES.REFCLK_N  [project net MD_PCIE1_4LANES.REFCLK_N]
PCIE1_REFCLK_P: MODULE1.BC18(PCIE1_REFCLK_P) ; port PCIE1_4LANES.REFCLK_P  [project net MD_PCIE1_4LANES.REFCLK_P]
PCIE1_RX0_N: MODULE1.BF16(PCIE1_RX0_M) ; port PCIE1_4LANES.RX0_N  [project net MD_PCIE1_4LANES.RX0_N]
PCIE1_RX0_P: MODULE1.BF17(PCIE1_RX0_P) ; port PCIE1_4LANES.RX0_P  [project net MD_PCIE1_4LANES.RX0_P]
PCIE1_RX1_N: MODULE1.BE15(PCIE1_RX1_M) ; port PCIE1_4LANES.RX1_N  [project net MD_PCIE1_4LANES.RX1_N]
PCIE1_RX1_P: MODULE1.BE16(PCIE1_RX1_P) ; port PCIE1_4LANES.RX1_P  [project net MD_PCIE1_4LANES.RX1_P]
PCIE1_RX2_N: MODULE1.BD14(PCIE1_RX2_M) ; port PCIE1_4LANES.RX2_N  [project net MD_PCIE1_4LANES.RX2_N]
PCIE1_RX2_P: MODULE1.BD15(PCIE1_RX2_P) ; port PCIE1_4LANES.RX2_P  [project net MD_PCIE1_4LANES.RX2_P]
PCIE1_RX3_N: MODULE1.BC13(PCIE1_RX3_M) ; port PCIE1_4LANES.RX3_N  [project net MD_PCIE1_4LANES.RX3_N]
PCIE1_RX3_P: MODULE1.BC14(PCIE1_RX3_P) ; port PCIE1_4LANES.RX3_P  [project net MD_PCIE1_4LANES.RX3_P]
PCIE1_TX0_N: MODULE1.BF12(PCIE1_TX0_M) ; port PCIE1_4LANES.TX0_N  [project net MD_PCIE1_4LANES.TX0_N]
PCIE1_TX0_P: MODULE1.BF13(PCIE1_TX0_P) ; port PCIE1_4LANES.TX0_P  [project net MD_PCIE1_4LANES.TX0_P]
PCIE1_TX1_N: MODULE1.BE11(PCIE1_TX1_M) ; port PCIE1_4LANES.TX1_N  [project net MD_PCIE1_4LANES.TX1_N]
PCIE1_TX1_P: MODULE1.BE12(PCIE1_TX1_P) ; port PCIE1_4LANES.TX1_P  [project net MD_PCIE1_4LANES.TX1_P]
PCIE1_TX2_N: MODULE1.BD10(PCIE1_TX2_M) ; port PCIE1_4LANES.TX2_N  [project net MD_PCIE1_4LANES.TX2_N]
PCIE1_TX2_P: MODULE1.BD11(PCIE1_TX2_P) ; port PCIE1_4LANES.TX2_P  [project net MD_PCIE1_4LANES.TX2_P]
PCIE1_TX3_N: MODULE1.BC9(PCIE1_TX3_M) ; port PCIE1_4LANES.TX3_N  [project net MD_PCIE1_4LANES.TX3_N]
PCIE1_TX3_P: MODULE1.BC10(PCIE1_TX3_P) ; port PCIE1_4LANES.TX3_P  [project net MD_PCIE1_4LANES.TX3_P]
SGMII0_RX_N: MODULE1.BF26(SGMII0_RX_M) ; port SGMII0.RX_N  [project net MD_SGMII0.RX_N]
SGMII0_RX_P: MODULE1.BE26(SGMII0_RX_P) ; port SGMII0.RX_P  [project net MD_SGMII0.RX_P]
SGMII0_TX_N: MODULE1.BC25(SGMII0_TX_M) ; port SGMII0.TX_N  [project net MD_SGMII0.TX_N]
SGMII0_TX_P: MODULE1.BC26(SGMII0_TX_P) ; port SGMII0.TX_P  [project net MD_SGMII0.TX_P]
USB0_HS_D_N: MODULE1.BD6(USB0_HS_DM) ; port USB0_3.1.HS_D_N  [project net MD_USB0_3.1.HS_D_N]
USB0_HS_D_P: MODULE1.BD7(USB0_HS_DP) ; port USB0_3.1.HS_D_P  [project net MD_USB0_3.1.HS_D_P]
USB0_SS_RX_N: MODULE1.BB1(USB0_SS_RX_M) ; port USB0_3.1.SS_RX_N  [project net MD_USB0_3.1.SS_RX_N]
USB0_SS_RX_P: MODULE1.BA1(USB0_SS_RX_P) ; port USB0_3.1.SS_RX_P  [project net MD_USB0_3.1.SS_RX_P]
USB0_SS_TX_N: MODULE1.BF6(CONN_USB0_SS_TX_M) ; port USB0_3.1.SS_TX_N  [project net MD_USB0_3.1.SS_TX_N]
USB0_SS_TX_P: MODULE1.BF5(CONN_USB0_SS_TX_P) ; port USB0_3.1.SS_TX_P  [project net MD_USB0_3.1.SS_TX_P]
USB1_HS_D_N: MODULE1.BF8(USB1_HS_DM) ; port USB1_2.0.HS_D_N  [project net MD_USB1_2.0.HS_D_N]
USB1_HS_D_P: MODULE1.BF9(USB1_HS_DP) ; port USB1_2.0.HS_D_P  [project net MD_USB1_2.0.HS_D_P]
NetMODULE1_B31: MODULE1.B31(GPIO_128) ; port LPASS_GPIO_128
NetMODULE1_D32: MODULE1.D32(GPIO_124) ; port LPASS_GPIO_124
NetMODULE1_E29: MODULE1.E29(GPIO_114) ; port LPASS_GPIO_114

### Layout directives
differential pair; differential pair class DIFF_MD_CSI0; net class NET_DIFF_CSI_DSI: CSI0_CK_N, CSI0_CK_P, CSI0_L0_N, CSI0_L0_P, CSI0_L1_N, CSI0_L1_P, CSI0_L2_N, CSI0_L2_P, CSI0_L3_N, CSI0_L3_P
differential pair; differential pair class DIFF_MD_CSI1; net class NET_DIFF_CSI_DSI: CSI1_CK_N, CSI1_CK_P, CSI1_L0_N, CSI1_L0_P, CSI1_L1_N, CSI1_L1_P, CSI1_L2_N, CSI1_L2_P, CSI1_L3_N, CSI1_L3_P
differential pair; differential pair class DIFF_MD_CSI2; net class NET_DIFF_CSI_DSI: CSI2_CK_N, CSI2_CK_P, CSI2_L0_N, CSI2_L0_P, CSI2_L1_N, CSI2_L1_P, CSI2_L2_N, CSI2_L2_P, CSI2_L3_N, CSI2_L3_P
differential pair; differential pair class DIFF_MD_DSI0; net class NET_DIFF_CSI_DSI: DSI0_CK_N, DSI0_CK_P, DSI0_L0_N, DSI0_L0_P, DSI0_L1_N, DSI0_L1_P, DSI0_L2_N, DSI0_L2_P, DSI0_L3_N, DSI0_L3_P
differential pair; differential pair class DIFF_MD_EDP; net class NET_DIFF_MD: EDP0_AUX_N, EDP0_AUX_P, EDP0_TX0_N, EDP0_TX0_P, EDP0_TX1_N, EDP0_TX1_P, EDP0_TX2_N, EDP0_TX2_P, EDP0_TX3_N, EDP0_TX3_P
differential pair; differential pair class DIFF_MD_SGMII; net class NET_DIFF_SGMII: MD_SGMII0.RX_N, MD_SGMII0.RX_P, MD_SGMII0.TX_N, MD_SGMII0.TX_P
differential pair; differential pair class DIFF_MD_USB0; net class DIFF_USB: MD_USB0_3.1.HS_D_N, MD_USB0_3.1.HS_D_P, MD_USB0_3.1.SS_RX_N, MD_USB0_3.1.SS_RX_P, MD_USB0_3.1.SS_TX_N, MD_USB0_3.1.SS_TX_P
differential pair; differential pair class DIFF_MD_PCIE0; net class NET_DIFF_PCIE: MD_PCIE0_2LANES.REFCLK_N, MD_PCIE0_2LANES.REFCLK_P, MD_PCIE0_2LANES.RX0_N, MD_PCIE0_2LANES.RX0_P, MD_PCIE0_2LANES.RX1_N, MD_PCIE0_2LANES.RX1_P, MD_PCIE0_2LANES.TX0_N, MD_PCIE0_2LANES.TX0_P, MD_PCIE0_2LANES.TX1_N, MD_PCIE0_2LANES.TX1_P
differential pair; differential pair class DIFF_MD_PCIE1; net class NET_DIFF_PCIE: MD_PCIE1_4LANES.REFCLK_N, MD_PCIE1_4LANES.REFCLK_P, MD_PCIE1_4LANES.RX0_N, MD_PCIE1_4LANES.RX0_P, MD_PCIE1_4LANES.RX1_N, MD_PCIE1_4LANES.RX1_P, MD_PCIE1_4LANES.RX2_N, MD_PCIE1_4LANES.RX2_P, MD_PCIE1_4LANES.RX3_N, MD_PCIE1_4LANES.RX3_P, MD_PCIE1_4LANES.TX0_N, MD_PCIE1_4LANES.TX0_P, MD_PCIE1_4LANES.TX1_N, MD_PCIE1_4LANES.TX1_P, MD_PCIE1_4LANES.TX2_N, MD_PCIE1_4LANES.TX2_P, MD_PCIE1_4LANES.TX3_N, MD_PCIE1_4LANES.TX3_P
net class NET_SOM_MD_SGMII0: GPIO_4, GPIO_5, GPIO_6, GPIO_50, MD_SGMII0.RX_N, MD_SGMII0.RX_P, MD_SGMII0.TX_N, MD_SGMII0.TX_P
net class NET_SOM_MD_USB0: MD_USB0_3.1.HS_D_N, MD_USB0_3.1.HS_D_P, MD_USB0_3.1.SS_RX_N, MD_USB0_3.1.SS_RX_P, MD_USB0_3.1.SS_TX_N, MD_USB0_3.1.SS_TX_P
net class NET_SOM_MD_USB1: MD_USB1_2.0.HS_D_N, MD_USB1_2.0.HS_D_P
differential pair; differential pair class DIFF_MD_USB1; net class DIFF_USB: MD_USB1_2.0.HS_D_N, MD_USB1_2.0.HS_D_P
net class NET_SOM_MD_GPIO: CLKREQ_N_1V8, CTS_1V8, GPIO_0, GPIO_2, GPIO_4, GPIO_5, GPIO_6, GPIO_7, GPIO_8, GPIO_21, GPIO_22, GPIO_23, GPIO_50, GPIO_53, GPIO_66, GPIO_76, GPIO_91, GPIO_97, GPIO_98, GPIO_102, MD_CCI_I2C0.SCL, MD_CCI_I2C0.SDA, MD_CCI_I2C2.SCL, MD_CCI_I2C2.SDA, MD_CCI_I2C3.SCL, MD_CCI_I2C3.SDA, MD_CCI_I2C4.SCL, MD_CCI_I2C4.SDA, MD_GPIO_3, MD_GPIO_10, MD_GPIO_11, MD_GPIO_12, MD_GPIO_13, MD_GPIO_14, MD_GPIO_15, MD_GPIO_16, MD_GPIO_17, MD_GPIO_18, MD_GPIO_19, MD_GPIO_20, MD_GPIO_24, MD_GPIO_25, MD_GPIO_26, MD_GPIO_27, MD_GPIO_28, MD_GPIO_29, MD_GPIO_30, MD_GPIO_33, MD_GPIO_34, MD_GPIO_35, MD_GPIO_36, MD_GPIO_37, MD_GPIO_38, MD_GPIO_39, MD_GPIO_40, MD_GPIO_41, MD_GPIO_42, MD_GPIO_43, MD_GPIO_44, MD_GPIO_45, MD_GPIO_46, MD_GPIO_47, MD_GPIO_48, MD_GPIO_49, MD_GPIO_51, MD_GPIO_52, MD_GPIO_54, MD_GPIO_55, MD_GPIO_56, MD_GPIO_63, MD_GPIO_64, MD_GPIO_65, MD_GPIO_67, MD_GPIO_68, MD_GPIO_69, MD_GPIO_70, MD_GPIO_71, MD_GPIO_73, MD_GPIO_74, MD_GPIO_75, MD_GPIO_77, MD_GPIO_78, MD_GPIO_79, MD_GPIO_80, MD_GPIO_81, MD_GPIO_82, MD_GPIO_83, MD_GPIO_85, MD_GPIO_86, MD_GPIO_87, MD_GPIO_88, MD_GPIO_89, MD_GPIO_90, MD_GPIO_92, MD_GPIO_93, MD_GPIO_94, MD_GPIO_95, MD_GPIO_96, MD_GPIO_99, MD_GPIO_100, MD_GPIO_101, MD_GPIO_103, MD_GPIO_104, MD_GPIO_105, MD_GPIO_106, MD_GPIO_107, MD_GPIO_108, MD_GPIO_109
net class NET_SOM_MD_EDP0: EDP0_AUX_N, EDP0_AUX_P, EDP0_TX0_N, EDP0_TX0_P, EDP0_TX1_N, EDP0_TX1_P, EDP0_TX2_N, EDP0_TX2_P, EDP0_TX3_N, EDP0_TX3_P
net class NET_SOM_MD_CSI0: CSI0_CK_N, CSI0_CK_P, CSI0_L0_N, CSI0_L0_P, CSI0_L1_N, CSI0_L1_P, CSI0_L2_N, CSI0_L2_P, CSI0_L3_N, CSI0_L3_P
net class NET_SOM_MD_CSI1: CSI1_CK_N, CSI1_CK_P, CSI1_L0_N, CSI1_L0_P, CSI1_L1_N, CSI1_L1_P, CSI1_L2_N, CSI1_L2_P, CSI1_L3_N, CSI1_L3_P
net class NET_SOM_MD_CSI2: CSI2_CK_N, CSI2_CK_P, CSI2_L0_N, CSI2_L0_P, CSI2_L1_N, CSI2_L1_P, CSI2_L2_N, CSI2_L2_P, CSI2_L3_N, CSI2_L3_P
net class NET_SOM_MD_DSI0: DSI0_CK_N, DSI0_CK_P, DSI0_L0_N, DSI0_L0_P, DSI0_L1_N, DSI0_L1_P, DSI0_L2_N, DSI0_L2_P, DSI0_L3_N, DSI0_L3_P
net class NET_SOM_MD_PCIE0: CLKREQ_N_1V8, GPIO_0, GPIO_2, MD_PCIE0_2LANES.REFCLK_N, MD_PCIE0_2LANES.REFCLK_P, MD_PCIE0_2LANES.RX0_N, MD_PCIE0_2LANES.RX0_P, MD_PCIE0_2LANES.RX1_N, MD_PCIE0_2LANES.RX1_P, MD_PCIE0_2LANES.TX0_N, MD_PCIE0_2LANES.TX0_P, MD_PCIE0_2LANES.TX1_N, MD_PCIE0_2LANES.TX1_P
net class NET_SOM_MD_PCIE1: GPIO_21, GPIO_22, GPIO_23, MD_PCIE1_4LANES.REFCLK_N, MD_PCIE1_4LANES.REFCLK_P, MD_PCIE1_4LANES.RX0_N, MD_PCIE1_4LANES.RX0_P, MD_PCIE1_4LANES.RX1_N, MD_PCIE1_4LANES.RX1_P, MD_PCIE1_4LANES.RX2_N, MD_PCIE1_4LANES.RX2_P, MD_PCIE1_4LANES.RX3_N, MD_PCIE1_4LANES.RX3_P, MD_PCIE1_4LANES.TX0_N, MD_PCIE1_4LANES.TX0_P, MD_PCIE1_4LANES.TX1_N, MD_PCIE1_4LANES.TX1_P, MD_PCIE1_4LANES.TX2_N, MD_PCIE1_4LANES.TX2_P, MD_PCIE1_4LANES.TX3_N, MD_PCIE1_4LANES.TX3_P
net class NET_SOM_MD_GPIO; net class NET_SOM_MD_GPIO_LPASS: I2S_DATA0, I2S_DATA1, I2S_SCK, I2S_WS, MD_LPASS_GPIO_110, MD_LPASS_GPIO_111, MD_LPASS_GPIO_112, MD_LPASS_GPIO_113, MD_LPASS_GPIO_115, MD_LPASS_GPIO_120, MD_LPASS_GPIO_121, MD_LPASS_GPIO_122, MD_LPASS_GPIO_123, MD_LPASS_GPIO_125, MD_LPASS_GPIO_126, MD_LPASS_GPIO_127, MD_LPASS_GPIO_129, MD_LPASS_GPIO_130, MD_LPASS_GPIO_131, MD_LPASS_GPIO_132, NetMODULE1_B31, NetMODULE1_D32, NetMODULE1_E29
net class NET_SOM_MD_BOOT: GPIO_7, GPIO_8, GPIO_53, GPIO_66, GPIO_76, GPIO_91, GPIO_97, GPIO_98, GPIO_102

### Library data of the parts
MODULE1 = M0029-A.19: as MODULE1 on sheet MODULE_SAIL

## Sheet MODULE_SAIL_FLASH.SchDoc: MODULE SAIL FLASH
size A3; Author: Silvio Navaretti; CompanyName: ARDUINO; DrawnBy: Silvio Navaretti; Engineer: Silvio Navaretti; Organization: ARDUINO; SheetNumber: 6; SheetTotal: 51; RevAuthor: Silvio Navaretti
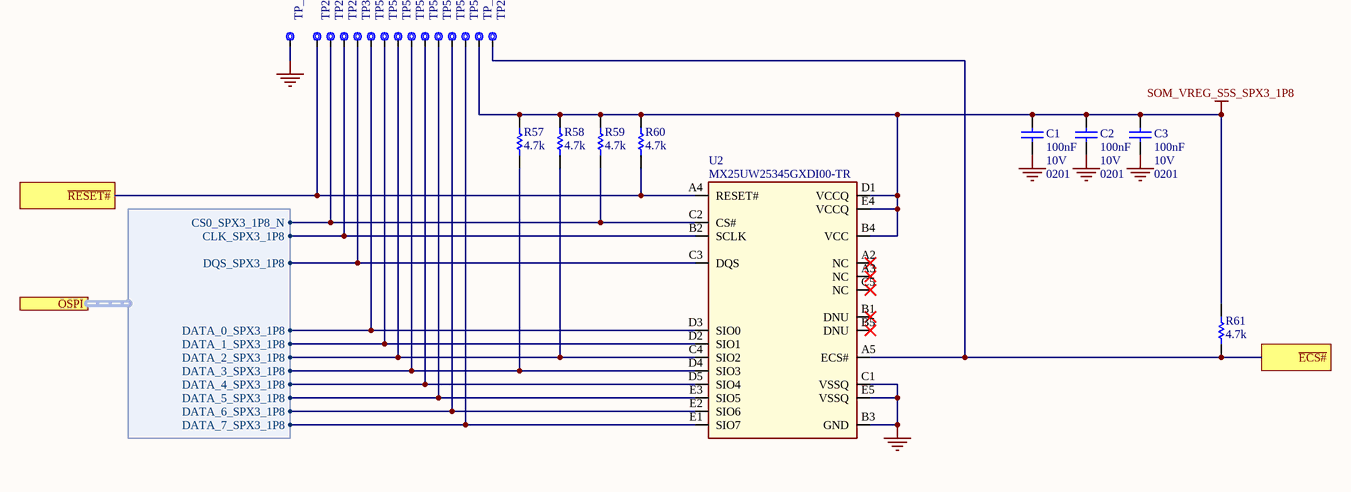
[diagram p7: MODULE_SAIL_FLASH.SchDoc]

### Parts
C1  value 100nF  Voltage: 10V  Case Code (Imperial): 0201  [CAP-0201]  (hidden comment: CL03A104KP3NNNC)
C2  value 100nF  Voltage: 10V  Case Code (Imperial): 0201  [CAP-0201]  (hidden comment: CL03A104KP3NNNC)
C3  value 100nF  Voltage: 10V  Case Code (Imperial): 0201  [CAP-0201]  (hidden comment: CL03A104KP3NNNC)
R57  value 4.7k  [RES-0201]  (hidden comment: RC0201FR-074K7L)
R58  value 4.7k  [RES-0201]  (hidden comment: RC0201FR-074K7L)
R59  value 4.7k  [RES-0201]  (hidden comment: RC0201FR-074K7L)
R60  value 4.7k  [RES-0201]  (hidden comment: RC0201FR-074K7L)
R61  value 4.7k  [RES-0201]  (hidden comment: RC0201FR-074K7L)
TP25  Test point 1.00mm  [TP-1.00MM]  (value not drawn)  (no BOM)
TP26  Test point 1.00mm  [TP-1.00MM]  (value not drawn)  (no BOM)
TP27  Test point 1.00mm  [TP-1.00MM]  (value not drawn)  (no BOM)
TP28  Test point 1.00mm  [TP-1.00MM]  (value not drawn)  (no BOM)
TP31  Test point 1.00mm  [TP-1.00MM]  (value not drawn)  (no BOM)
TP50  Test point 1.00mm  [TP-1.00MM]  (value not drawn)  (no BOM)
TP51  Test point 1.00mm  [TP-1.00MM]  (value not drawn)  (no BOM)
TP52  Test point 1.00mm  [TP-1.00MM]  (value not drawn)  (no BOM)
TP53  Test point 1.00mm  [TP-1.00MM]  (value not drawn)  (no BOM)
TP54  Test point 1.00mm  [TP-1.00MM]  (value not drawn)  (no BOM)
TP55  Test point 1.00mm  [TP-1.00MM]  (value not drawn)  (no BOM)
TP56  Test point 1.00mm  [TP-1.00MM]  (value not drawn)  (no BOM)
TP57  Test point 1.00mm  [TP-1.00MM]  (value not drawn)  (no BOM)
TP_FLASH_SAIL_1V8  Test point 1.00mm  [TP-1.00MM]  (value not drawn)  (no BOM)
TP_FLASH_SAIL_GND  Test point 1.00mm  [TP-1.00MM]  (value not drawn)  (no BOM)
U2  MX25UW25345GXDI00-TR  [MX25UW25345GXDI00-TR]

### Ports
OSPI (harness SOM_SAIL_QSPI0), ~{ECS#}, ~{RESET#}

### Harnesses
SOM_SAIL_QSPI0: DATA_0_SPX3_1P8, DATA_1_SPX3_1P8, DATA_2_SPX3_1P8, DATA_3_SPX3_1P8, DATA_4_SPX3_1P8, DATA_5_SPX3_1P8, DATA_6_SPX3_1P8, DATA_7_SPX3_1P8, CS0_SPX3_1P8_N, CLK_SPX3_1P8, DQS_SPX3_1P8

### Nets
GND: C1.1 C2.1 C3.1 TP_FLASH_SAIL_GND.X U2.B3(GND) U2.C1(VSSQ) U2.E5(VSSQ)
SOM_VREG_S5S_SPX3_1P8: C1.2 C2.2 C3.2 R57.2 R58.2 R59.2 R60.2 R61.2 TP_FLASH_SAIL_1V8.X U2.B4(VCC) U2.D1(VCCQ) U2.E4(VCCQ)
NetMODULE1_BA29: R59.1 TP27.X U2.C2(CS#) ; port OSPI.CS0_SPX3_1P8_N
NetMODULE1_BB28: TP54.X U2.D5(SIO4) ; port OSPI.DATA_4_SPX3_1P8
NetMODULE1_BB29: R58.1 TP52.X U2.C4(SIO2) ; port OSPI.DATA_2_SPX3_1P8
NetMODULE1_BC28: TP31.X U2.C3(DQS) ; port OSPI.DQS_SPX3_1P8
NetMODULE1_BC29: TP28.X U2.B2(SCLK) ; port OSPI.CLK_SPX3_1P8
NetMODULE1_BD28: TP55.X U2.E3(SIO5) ; port OSPI.DATA_5_SPX3_1P8
NetMODULE1_BD29: R57.1 TP53.X U2.D4(SIO3) ; port OSPI.DATA_3_SPX3_1P8
NetMODULE1_BD41: R60.1 TP26.X U2.A4(RESET#) ; port ~{RESET#}
NetMODULE1_BE28: TP56.X U2.E2(SIO6) ; port OSPI.DATA_6_SPX3_1P8
NetMODULE1_BE29: TP50.X U2.D3(SIO0) ; port OSPI.DATA_0_SPX3_1P8
NetMODULE1_BF28: TP51.X U2.D2(SIO1) ; port OSPI.DATA_1_SPX3_1P8
NetMODULE1_BF29: TP57.X U2.E1(SIO7) ; port OSPI.DATA_7_SPX3_1P8
NetR61_1: R61.1 TP25.X U2.A5(ECS#) ; port ~{ECS#}

Not connected (* = marked no-connect by the designer): U2 A2(NC)* A3(NC)* B1(DNU)* B5(DNU)* C5(NC)*

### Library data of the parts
C1-C3 = C0113-A.6: CAP CHIP 0201 100nF 10% 10V X5R; Manufacturer: Samsung Electro-Mechanics; Code Arduino: C0113
R57-R61 = R0151-A.21: RES CHIP 0201 4k7 1% 1/20W; Manufacturer: Yageo; Temperature coefficient: 200ppm; Power: 50mW; Code Arduino: A5521
TP25-TP28 TP31 TP50-TP57 TP_FLASH_SAIL_1V8 TP_FLASH_SAIL_GND = UT0013-A.6: Part Number: This is not a component
U2 = U0506-A.2: IC NOR FLASH, VDD 1.8V, OSPI, 256Mb x1/x8, BGA24 6x8mm; Manufacturer: Macronix; Code Arduino: U0506

## Sheet MODULE_STRAPS_MD.SchDoc: MODULE STRAPS MD
size A3; Author: Silvio Navaretti; CompanyName: ARDUINO; DrawnBy: Silvio Navaretti; Engineer: Silvio Navaretti; Organization: ARDUINO; SheetNumber: 7; SheetTotal: 51; RevAuthor: Silvio Navaretti
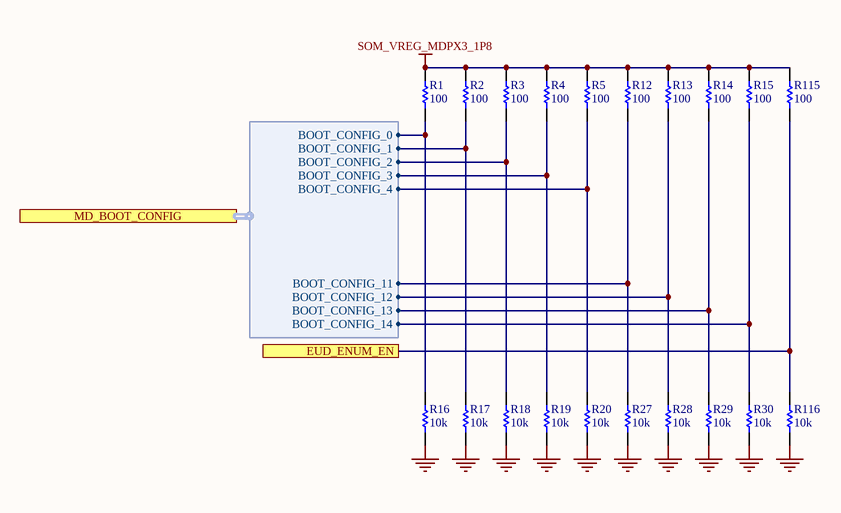
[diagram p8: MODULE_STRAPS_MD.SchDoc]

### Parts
R1  value 100  [RES-0201]  (hidden comment: RC0201FR-07100RL)
R2  value 100  [RES-0201]  (hidden comment: RC0201FR-07100RL)
R3  value 100  [RES-0201]  (hidden comment: RC0201FR-07100RL)
R4  value 100  [RES-0201]  (hidden comment: RC0201FR-07100RL)
R5  value 100  [RES-0201]  (hidden comment: RC0201FR-07100RL)
R12  value 100  [RES-0201]  (hidden comment: RC0201FR-07100RL)
R13  value 100  [RES-0201]  (hidden comment: RC0201FR-07100RL)
R14  value 100  [RES-0201]  (hidden comment: RC0201FR-07100RL)
R15  value 100  [RES-0201]  (hidden comment: RC0201FR-07100RL)
R16  value 10k  [RES-0201]  (hidden comment: RC0201FR-0710KL)
R17  value 10k  [RES-0201]  (hidden comment: RC0201FR-0710KL)
R18  value 10k  [RES-0201]  (hidden comment: RC0201FR-0710KL)
R19  value 10k  [RES-0201]  (hidden comment: RC0201FR-0710KL)
R20  value 10k  [RES-0201]  (hidden comment: RC0201FR-0710KL)
R27  value 10k  [RES-0201]  (hidden comment: RC0201FR-0710KL)
R28  value 10k  [RES-0201]  (hidden comment: RC0201FR-0710KL)
R29  value 10k  [RES-0201]  (hidden comment: RC0201FR-0710KL)
R30  value 10k  [RES-0201]  (hidden comment: RC0201FR-0710KL)
R115  value 100  [RES-0201]  (hidden comment: RC0201FR-07100RL)
R116  value 10k  [RES-0201]  (hidden comment: RC0201FR-0710KL)

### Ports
EUD_ENUM_EN, MD_BOOT_CONFIG (harness SOM_MD_BOOT_CONFIG)

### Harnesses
SOM_MD_BOOT_CONFIG: BOOT_CONFIG_0, BOOT_CONFIG_1, BOOT_CONFIG_2, BOOT_CONFIG_3, BOOT_CONFIG_4, BOOT_CONFIG_11, BOOT_CONFIG_12, BOOT_CONFIG_13, BOOT_CONFIG_14

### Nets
GND: R16.1 R17.1 R18.1 R19.1 R20.1 R27.1 R28.1 R29.1 R30.1 R116.1
SOM_VREG_MDPX3_1P8: R1.1 R2.1 R3.1 R4.1 R5.1 R12.1 R13.1 R14.1 R15.1 R115.1
GPIO_7: R13.2 R28.2 ; port MD_BOOT_CONFIG.BOOT_CONFIG_12
GPIO_8: R15.2 R30.2 ; port MD_BOOT_CONFIG.BOOT_CONFIG_14
GPIO_53: R12.2 R27.2 ; port MD_BOOT_CONFIG.BOOT_CONFIG_11
GPIO_66: R14.2 R29.2 ; port MD_BOOT_CONFIG.BOOT_CONFIG_13
GPIO_76: R2.2 R17.2 ; port MD_BOOT_CONFIG.BOOT_CONFIG_1
GPIO_91: R1.2 R16.2 ; port MD_BOOT_CONFIG.BOOT_CONFIG_0
GPIO_97: R3.2 R18.2 ; port MD_BOOT_CONFIG.BOOT_CONFIG_2
GPIO_98: R4.2 R19.2 ; port MD_BOOT_CONFIG.BOOT_CONFIG_3
GPIO_102: R5.2 R20.2 ; port MD_BOOT_CONFIG.BOOT_CONFIG_4
MD_GPIO_99: R115.2 R116.2 ; port EUD_ENUM_EN

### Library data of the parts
R1-R5 R12-R15 R115 = R0235-A.13: RES CHIP 0201 100R 1% 1/20W; Manufacturer: YAGEO; Power: 50mW; Temperature coefficient: 200ppm; Code Arduino: R0235
R16-R20 R27-R30 R116 = R0145-A.21: RES CHIP 0201 10k 1% 1/20W; Manufacturer: Yageo; Power: 50mW; Temperature coefficient: 200ppm; Code Arduino: R0145

## Sheet MODULE_STRAPS_SAIL.SchDoc: MODULE STRAPS SAIL
size A3; Author: Silvio Navaretti; CompanyName: ARDUINO; DrawnBy: Silvio Navaretti; Engineer: Silvio Navaretti; Organization: ARDUINO; SheetNumber: 8; SheetTotal: 51; RevAuthor: Silvio Navaretti
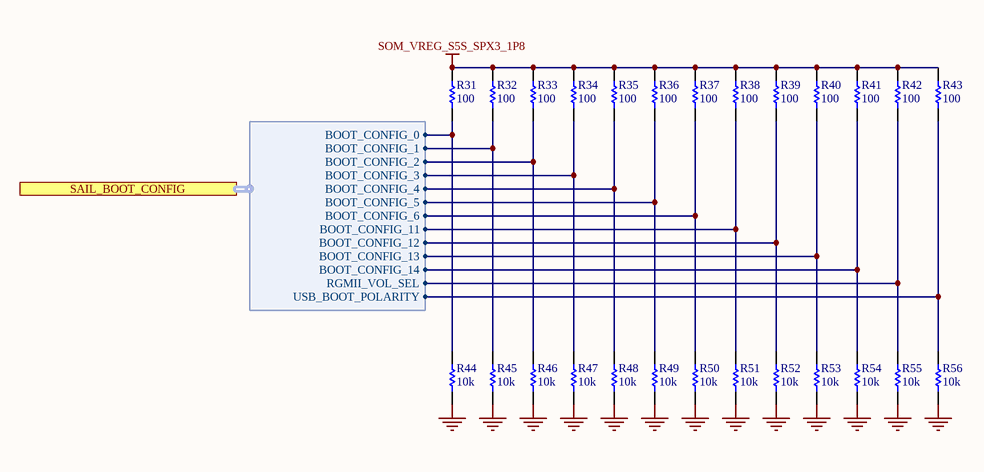
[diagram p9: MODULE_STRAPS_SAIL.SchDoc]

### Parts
R31  value 100  [RES-0201]  (hidden comment: RC0201FR-07100RL)
R32  value 100  [RES-0201]  (hidden comment: RC0201FR-07100RL)
R33  value 100  [RES-0201]  (hidden comment: RC0201FR-07100RL)
R34  value 100  [RES-0201]  (hidden comment: RC0201FR-07100RL)
R35  value 100  [RES-0201]  (hidden comment: RC0201FR-07100RL)
R36  value 100  [RES-0201]  (hidden comment: RC0201FR-07100RL)
R37  value 100  [RES-0201]  (hidden comment: RC0201FR-07100RL)
R38  value 100  [RES-0201]  (hidden comment: RC0201FR-07100RL)
R39  value 100  [RES-0201]  (hidden comment: RC0201FR-07100RL)
R40  value 100  [RES-0201]  (hidden comment: RC0201FR-07100RL)
R41  value 100  [RES-0201]  (hidden comment: RC0201FR-07100RL)
R42  value 100  [RES-0201]  (hidden comment: RC0201FR-07100RL)
R43  value 100  [RES-0201]  (hidden comment: RC0201FR-07100RL)
R44  value 10k  [RES-0201]  (hidden comment: RC0201FR-0710KL)
R45  value 10k  [RES-0201]  (hidden comment: RC0201FR-0710KL)
R46  value 10k  [RES-0201]  (hidden comment: RC0201FR-0710KL)
R47  value 10k  [RES-0201]  (hidden comment: RC0201FR-0710KL)
R48  value 10k  [RES-0201]  (hidden comment: RC0201FR-0710KL)
R49  value 10k  [RES-0201]  (hidden comment: RC0201FR-0710KL)
R50  value 10k  [RES-0201]  (hidden comment: RC0201FR-0710KL)
R51  value 10k  [RES-0201]  (hidden comment: RC0201FR-0710KL)
R52  value 10k  [RES-0201]  (hidden comment: RC0201FR-0710KL)
R53  value 10k  [RES-0201]  (hidden comment: RC0201FR-0710KL)
R54  value 10k  [RES-0201]  (hidden comment: RC0201FR-0710KL)
R55  value 10k  [RES-0201]  (hidden comment: RC0201FR-0710KL)
R56  value 10k  [RES-0201]  (hidden comment: RC0201FR-0710KL)

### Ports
SAIL_BOOT_CONFIG (harness SOM_SAIL_BOOT_CONFIG)

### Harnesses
SOM_SAIL_BOOT_CONFIG: BOOT_CONFIG_0, BOOT_CONFIG_1, BOOT_CONFIG_2, BOOT_CONFIG_3, BOOT_CONFIG_4, BOOT_CONFIG_5, BOOT_CONFIG_6, BOOT_CONFIG_11, BOOT_CONFIG_12, BOOT_CONFIG_13, BOOT_CONFIG_14, RGMII_VOL_SEL, USB_BOOT_POLARITY

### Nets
GND: R44.1 R45.1 R46.1 R47.1 R48.1 R49.1 R50.1 R51.1 R52.1 R53.1 R54.1 R55.1 R56.1
SOM_VREG_S5S_SPX3_1P8: R31.1 R32.1 R33.1 R34.1 R35.1 R36.1 R37.1 R38.1 R39.1 R40.1 R41.1 R42.1 R43.1
RTSS_IO_4: R43.2 R56.2 ; port SAIL_BOOT_CONFIG.USB_BOOT_POLARITY
RTSS_IO_6: R40.2 R53.2 ; port SAIL_BOOT_CONFIG.BOOT_CONFIG_13
RTSS_IO_7: R41.2 R54.2 ; port SAIL_BOOT_CONFIG.BOOT_CONFIG_14
RTSS_IO_10: R32.2 R45.2 ; port SAIL_BOOT_CONFIG.BOOT_CONFIG_1
RTSS_IO_11: R33.2 R46.2 ; port SAIL_BOOT_CONFIG.BOOT_CONFIG_2
RTSS_IO_12: R34.2 R47.2 ; port SAIL_BOOT_CONFIG.BOOT_CONFIG_3
RTSS_IO_14: R35.2 R48.2 ; port SAIL_BOOT_CONFIG.BOOT_CONFIG_4
RTSS_IO_15: R36.2 R49.2 ; port SAIL_BOOT_CONFIG.BOOT_CONFIG_5
RTSS_IO_16: R38.2 R51.2 ; port SAIL_BOOT_CONFIG.BOOT_CONFIG_11
RTSS_IO_17: R39.2 R52.2 ; port SAIL_BOOT_CONFIG.BOOT_CONFIG_12
RTSS_IO_18: R37.2 R50.2 ; port SAIL_BOOT_CONFIG.BOOT_CONFIG_6
RTSS_IO_21: R42.2 R55.2 ; port SAIL_BOOT_CONFIG.RGMII_VOL_SEL
RTSS_IO_51: R31.2 R44.2 ; port SAIL_BOOT_CONFIG.BOOT_CONFIG_0

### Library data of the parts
R31-R43 = R0235-A.13: as R1 on sheet MODULE_STRAPS_MD
R44-R56 = R0145-A.21: as R16-R20 on sheet MODULE_STRAPS_MD

## Sheet MODULE_CONTROL.SchDoc: MODULE CONTROL
size A3; SheetNumber: 5; SheetTotal: 51
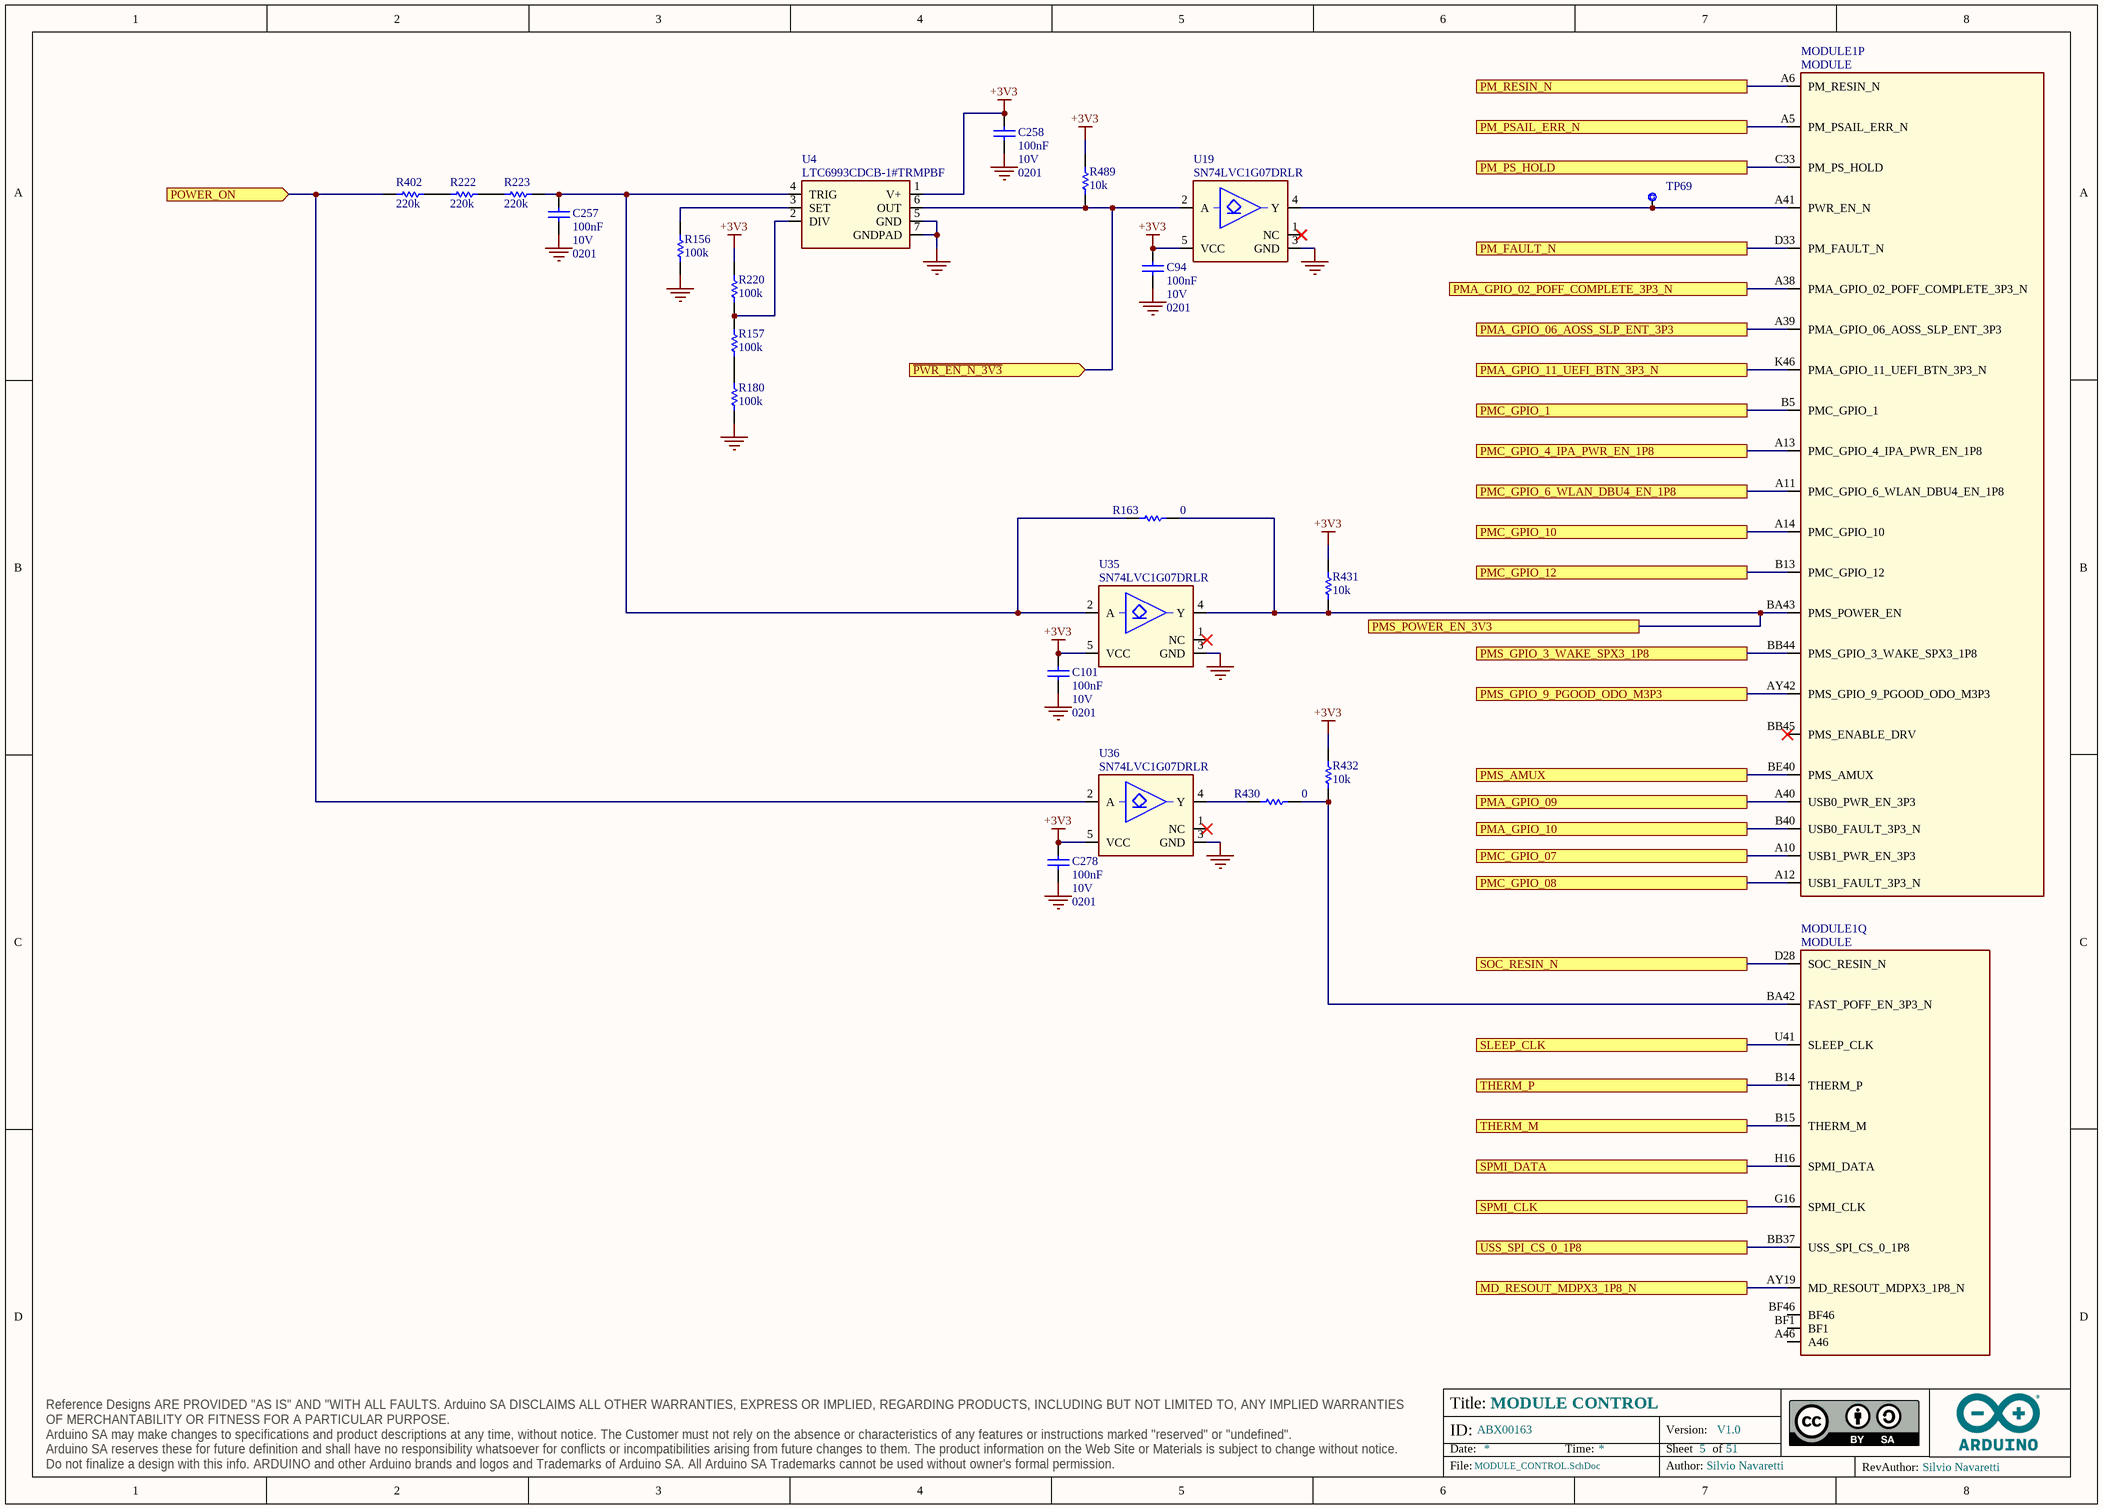
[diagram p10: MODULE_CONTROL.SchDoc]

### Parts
C94  value 100nF  Voltage: 10V  Case Code (Imperial): 0201  [CAP-0201]  (hidden comment: CL03A104KP3NNNC)
C101  value 100nF  Voltage: 10V  Case Code (Imperial): 0201  [CAP-0201]  (hidden comment: CL03A104KP3NNNC)
C257  value 100nF  Voltage: 10V  Case Code (Imperial): 0201  [CAP-0201]  (hidden comment: CL03A104KP3NNNC)
C258  value 100nF  Voltage: 10V  Case Code (Imperial): 0201  [CAP-0201]  (hidden comment: CL03A104KP3NNNC)
C278  value 100nF  Voltage: 10V  Case Code (Imperial): 0201  [CAP-0201]  (hidden comment: CL03A104KP3NNNC)
MODULE1  MODULE  [MODULE]  (parts P,Q of 22)
R156  value 100k  [RES-0201]  (hidden comment: RC0201FR-07100KL)
R157  value 100k  [RES-0201]  (hidden comment: RC0201FR-07100KL)
R163  value 0  [RES-0201]  (hidden comment: CRCW02010000Z0ED)
R180  value 100k  [RES-0201]  (hidden comment: RC0201FR-07100KL)
R220  value 100k  [RES-0201]  (hidden comment: RC0201FR-07100KL)
R222  value 220k  [RES-0201]  (hidden comment: AC0201FR-07220KL)
R223  value 220k  [RES-0201]  (hidden comment: AC0201FR-07220KL)
R402  value 220k  [RES-0201]  (hidden comment: AC0201FR-07220KL)
R430  value 0  [RES-0201]  (hidden comment: CRCW02010000Z0ED)
R431  value 10k  [RES-0201]  (hidden comment: RC0201FR-0710KL)
R432  value 10k  [RES-0201]  (hidden comment: RC0201FR-0710KL)
R489  value 10k  [RES-0201]  (hidden comment: RC0201FR-0710KL)
TP69  Test point 1.00mm  [TP-1.00MM]  (value not drawn)  (no BOM)
U4  LTC6993CDCB-1#TRMPBF  [AD DCB DFN 6 pin 2x3mm pitch 0.5mm]
U19  SN74LVC1G07DRLR  [TI DRL DRL0005A]
U35  SN74LVC1G07DRLR  [TI DRL DRL0005A]
U36  SN74LVC1G07DRLR  [TI DRL DRL0005A]

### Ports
MD_RESOUT_MDPX3_1P8_N, PM_FAULT_N, PM_PS_HOLD, PM_PSAIL_ERR_N, PM_RESIN_N, PMA_GPIO_02_POFF_COMPLETE_3P3_N, PMA_GPIO_06_AOSS_SLP_ENT_3P3, PMA_GPIO_09, PMA_GPIO_10, PMA_GPIO_11_UEFI_BTN_3P3_N, PMC_GPIO_1, PMC_GPIO_4_IPA_PWR_EN_1P8, PMC_GPIO_6_WLAN_DBU4_EN_1P8, PMC_GPIO_07, PMC_GPIO_08, PMC_GPIO_10, PMC_GPIO_12, PMS_AMUX, PMS_GPIO_3_WAKE_SPX3_1P8, PMS_GPIO_9_PGOOD_ODO_M3P3, PMS_POWER_EN_3V3, POWER_ON (in), SLEEP_CLK, SOC_RESIN_N, SPMI_CLK, SPMI_DATA, THERM_M, THERM_P, USS_SPI_CS_0_1P8, ~{PWR_EN_N_3V3} (in)

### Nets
+3V3: C94.2 C101.2 C258.2 C278.2 R220.2 R431.1 R432.1 R489.1 U4.1(V+) U19.5(VCC) U35.5(VCC) U36.5(VCC)
GND: C94.1 C101.1 C257.1 C258.1 C278.1 R156.1 R180.1 U4.5(GND) U4.7(GNDPAD) U19.3(GND) U35.3(GND) U36.3(GND)
PM_PS_HOLD: MODULE1.C33(PM_PS_HOLD) ; port PM_PS_HOLD
SLEEP_CLK: MODULE1.U41(SLEEP_CLK) ; port SLEEP_CLK
NetC257_2: C257.2 R163.2 R223.1 U4.4(TRIG) U35.2(A)
NetMODULE1_A5: MODULE1.A5(PM_PSAIL_ERR_N) ; port PM_PSAIL_ERR_N
NetMODULE1_A6: MODULE1.A6(PM_RESIN_N) ; port PM_RESIN_N
NetMODULE1_A10: MODULE1.A10(USB1_PWR_EN_3P3) ; port PMC_GPIO_07
NetMODULE1_A11: MODULE1.A11(PMC_GPIO_6_WLAN_DBU4_EN_1P8) ; port PMC_GPIO_6_WLAN_DBU4_EN_1P8
NetMODULE1_A12: MODULE1.A12(USB1_FAULT_3P3_N) ; port PMC_GPIO_08
NetMODULE1_A13: MODULE1.A13(PMC_GPIO_4_IPA_PWR_EN_1P8) ; port PMC_GPIO_4_IPA_PWR_EN_1P8
NetMODULE1_A14: MODULE1.A14(PMC_GPIO_10) ; port PMC_GPIO_10
NetMODULE1_A38: MODULE1.A38(PMA_GPIO_02_POFF_COMPLETE_3P3_N) ; port PMA_GPIO_02_POFF_COMPLETE_3P3_N
NetMODULE1_A39: MODULE1.A39(PMA_GPIO_06_AOSS_SLP_ENT_3P3) ; port PMA_GPIO_06_AOSS_SLP_ENT_3P3
NetMODULE1_A40: MODULE1.A40(USB0_PWR_EN_3P3) ; port PMA_GPIO_09
NetMODULE1_A41: MODULE1.A41(PWR_EN_N) TP69.X U19.4(Y)
NetMODULE1_AY19: MODULE1.AY19(MD_RESOUT_MDPX3_1P8_N) ; port MD_RESOUT_MDPX3_1P8_N
NetMODULE1_AY42: MODULE1.AY42(PMS_GPIO_9_PGOOD_ODO_M3P3) ; port PMS_GPIO_9_PGOOD_ODO_M3P3
NetMODULE1_B5: MODULE1.B5(PMC_GPIO_1) ; port PMC_GPIO_1
NetMODULE1_B13: MODULE1.B13(PMC_GPIO_12) ; port PMC_GPIO_12
NetMODULE1_B14: MODULE1.B14(THERM_P) ; port THERM_P
NetMODULE1_B15: MODULE1.B15(THERM_M) ; port THERM_M
NetMODULE1_B40: MODULE1.B40(USB0_FAULT_3P3_N) ; port PMA_GPIO_10
NetMODULE1_BA42: MODULE1.BA42(FAST_POFF_EN_3P3_N) R430.1 R432.2
NetMODULE1_BA43: MODULE1.BA43(PMS_POWER_EN) R163.1 R431.2 U35.4(Y) ; port PMS_POWER_EN_3V3
NetMODULE1_BB37: MODULE1.BB37(USS_SPI_CS_0_1P8) ; port USS_SPI_CS_0_1P8
NetMODULE1_BB44: MODULE1.BB44(PMS_GPIO_3_WAKE_SPX3_1P8) ; port PMS_GPIO_3_WAKE_SPX3_1P8
NetMODULE1_BE40: MODULE1.BE40(PMS_AMUX) ; port PMS_AMUX
NetMODULE1_D28: MODULE1.D28(SOC_RESIN_N) ; port SOC_RESIN_N
NetMODULE1_D33: MODULE1.D33(PM_FAULT_N) ; port PM_FAULT_N
NetMODULE1_G16: MODULE1.G16(SPMI_CLK) ; port SPMI_CLK
NetMODULE1_H16: MODULE1.H16(SPMI_DATA) ; port SPMI_DATA
NetMODULE1_K46: MODULE1.K46(PMA_GPIO_11_UEFI_BTN_3P3_N) ; port PMA_GPIO_11_UEFI_BTN_3P3_N
NetR156_2: R156.2 U4.3(SET)
NetR157_1: R157.1 R180.2
NetR157_2: R157.2 R220.1 U4.2(DIV)
NetR222_1: R222.1 R223.2
NetR222_2: R222.2 R402.1
NetR349_2: R402.2 U36.2(A) ; port POWER_ON
NetR350_2: R489.2 U4.6(OUT) U19.2(A) ; port ~{PWR_EN_N_3V3}
NetR430_2: R430.2 U36.4(Y)

Not connected (* = marked no-connect by the designer): MODULE1 A46 BB45(PMS_ENABLE_DRV)* BF1 BF46; U19 1(NC)*; U35 1(NC)*; U36 1(NC)*

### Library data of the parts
C94 C101 C257 C258 C278 = C0113-A.6: as C1-C3 on sheet MODULE_SAIL_FLASH
MODULE1 = M0029-A.19: as MODULE1 on sheet MODULE_SAIL
R156 R157 R180 R220 = R0146-A.21: RES CHIP 0201 100k 1% 1/20W; Manufacturer: Yageo; Power: 50mW; Temperature coefficient: 200ppm; Code Arduino: R0146
R163 R430 = R0140-A.21: RES CHIP 0201 0R; Manufacturer: Vishay; Temperature coefficient: 0ppm; Code Arduino: R0140; Power: 50mW; Tolerance: 0%
R222 R223 R402 = R0199-A.20: RES CHIP 0201 220k 1% 1/20W; Manufacturer: Yageo; Temperature coefficient: 200ppm; Power: 50mW; Code Arduino: R0199
R431 R432 R489 = R0145-A.21: as R16-R20 on sheet MODULE_STRAPS_MD
TP69 = UT0013-A.6: Part Number: This is not a component
U4 = U0524-A.1: IC monostable multivibrator programmable pulse 1us to 33.6 DFN6 2x3mm; Manufacturer: Analog Devices; Code Arduino: U0524
U19 U35 U36 = U0494-A.2: IC buffer open drain, 1.65V to 5.5V, 32mA sink current, SOT-5X3 1.6mmx1.6mm; Manufacturer: Texas Instruments; Code Arduino: U0494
